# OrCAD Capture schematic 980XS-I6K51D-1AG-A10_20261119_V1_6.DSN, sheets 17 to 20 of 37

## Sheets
17 P0011_S1_POWER: size A2
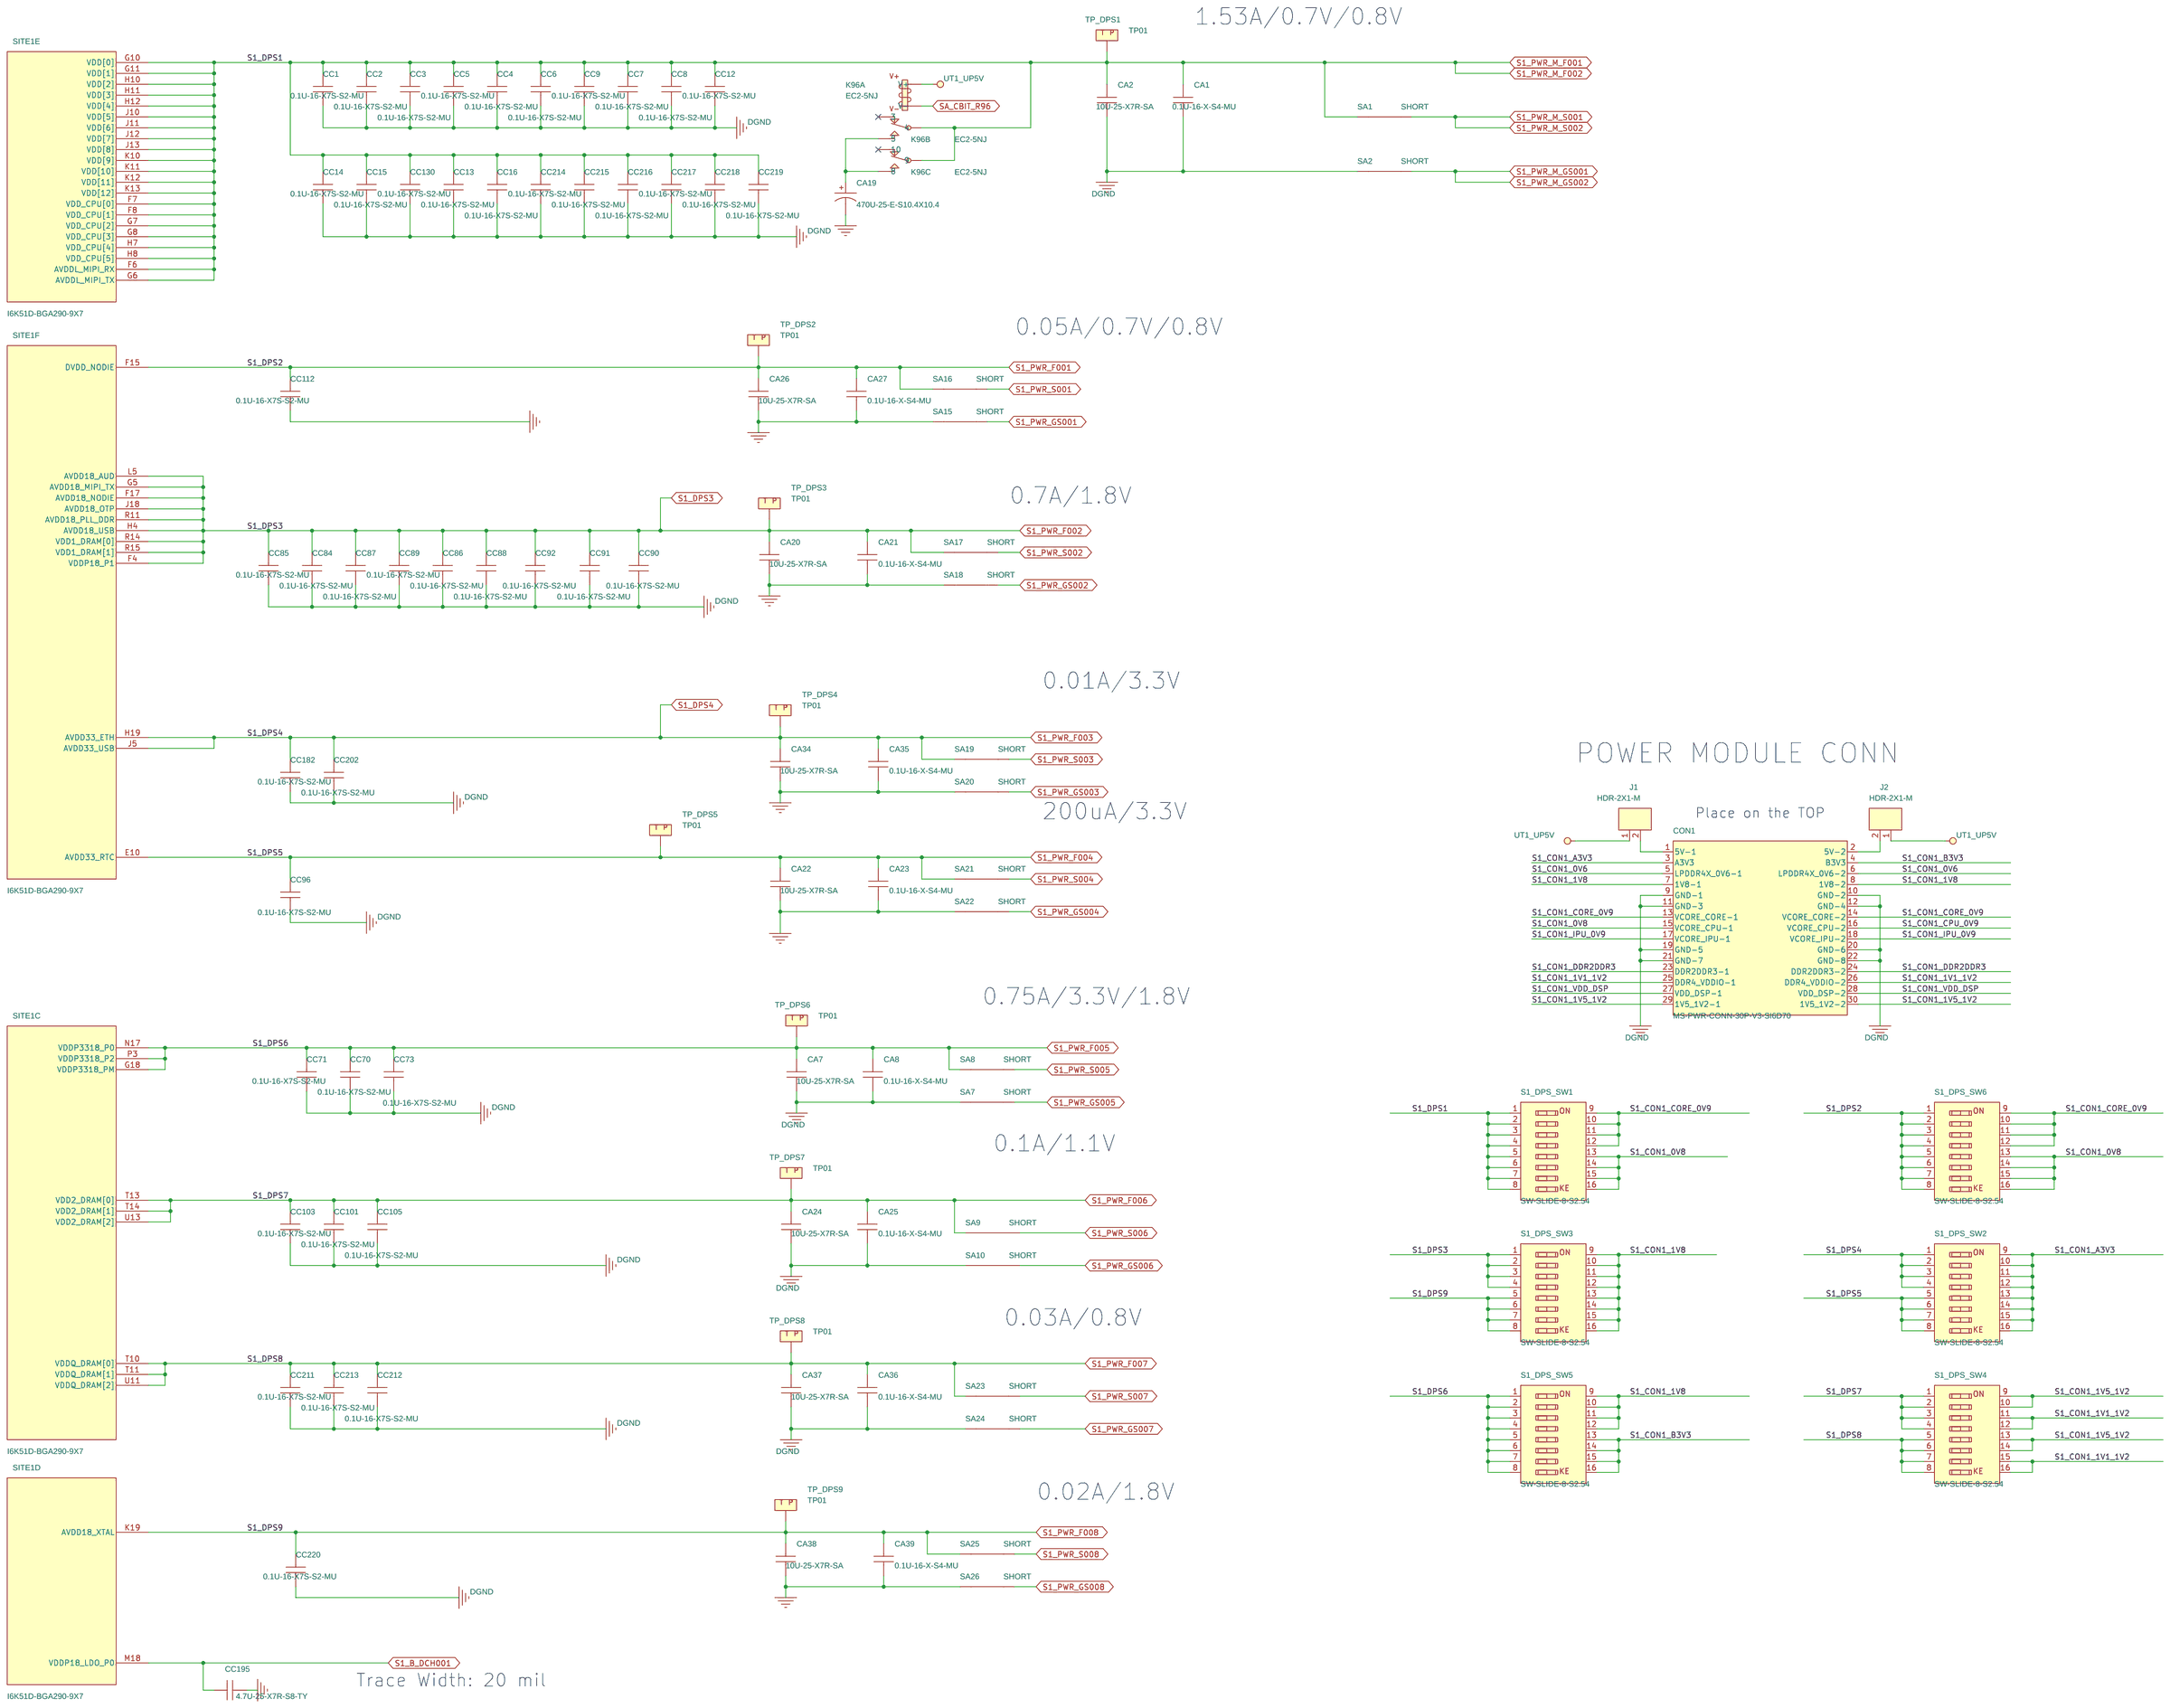
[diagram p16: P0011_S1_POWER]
18 P0013_S1_MIPI: size A2
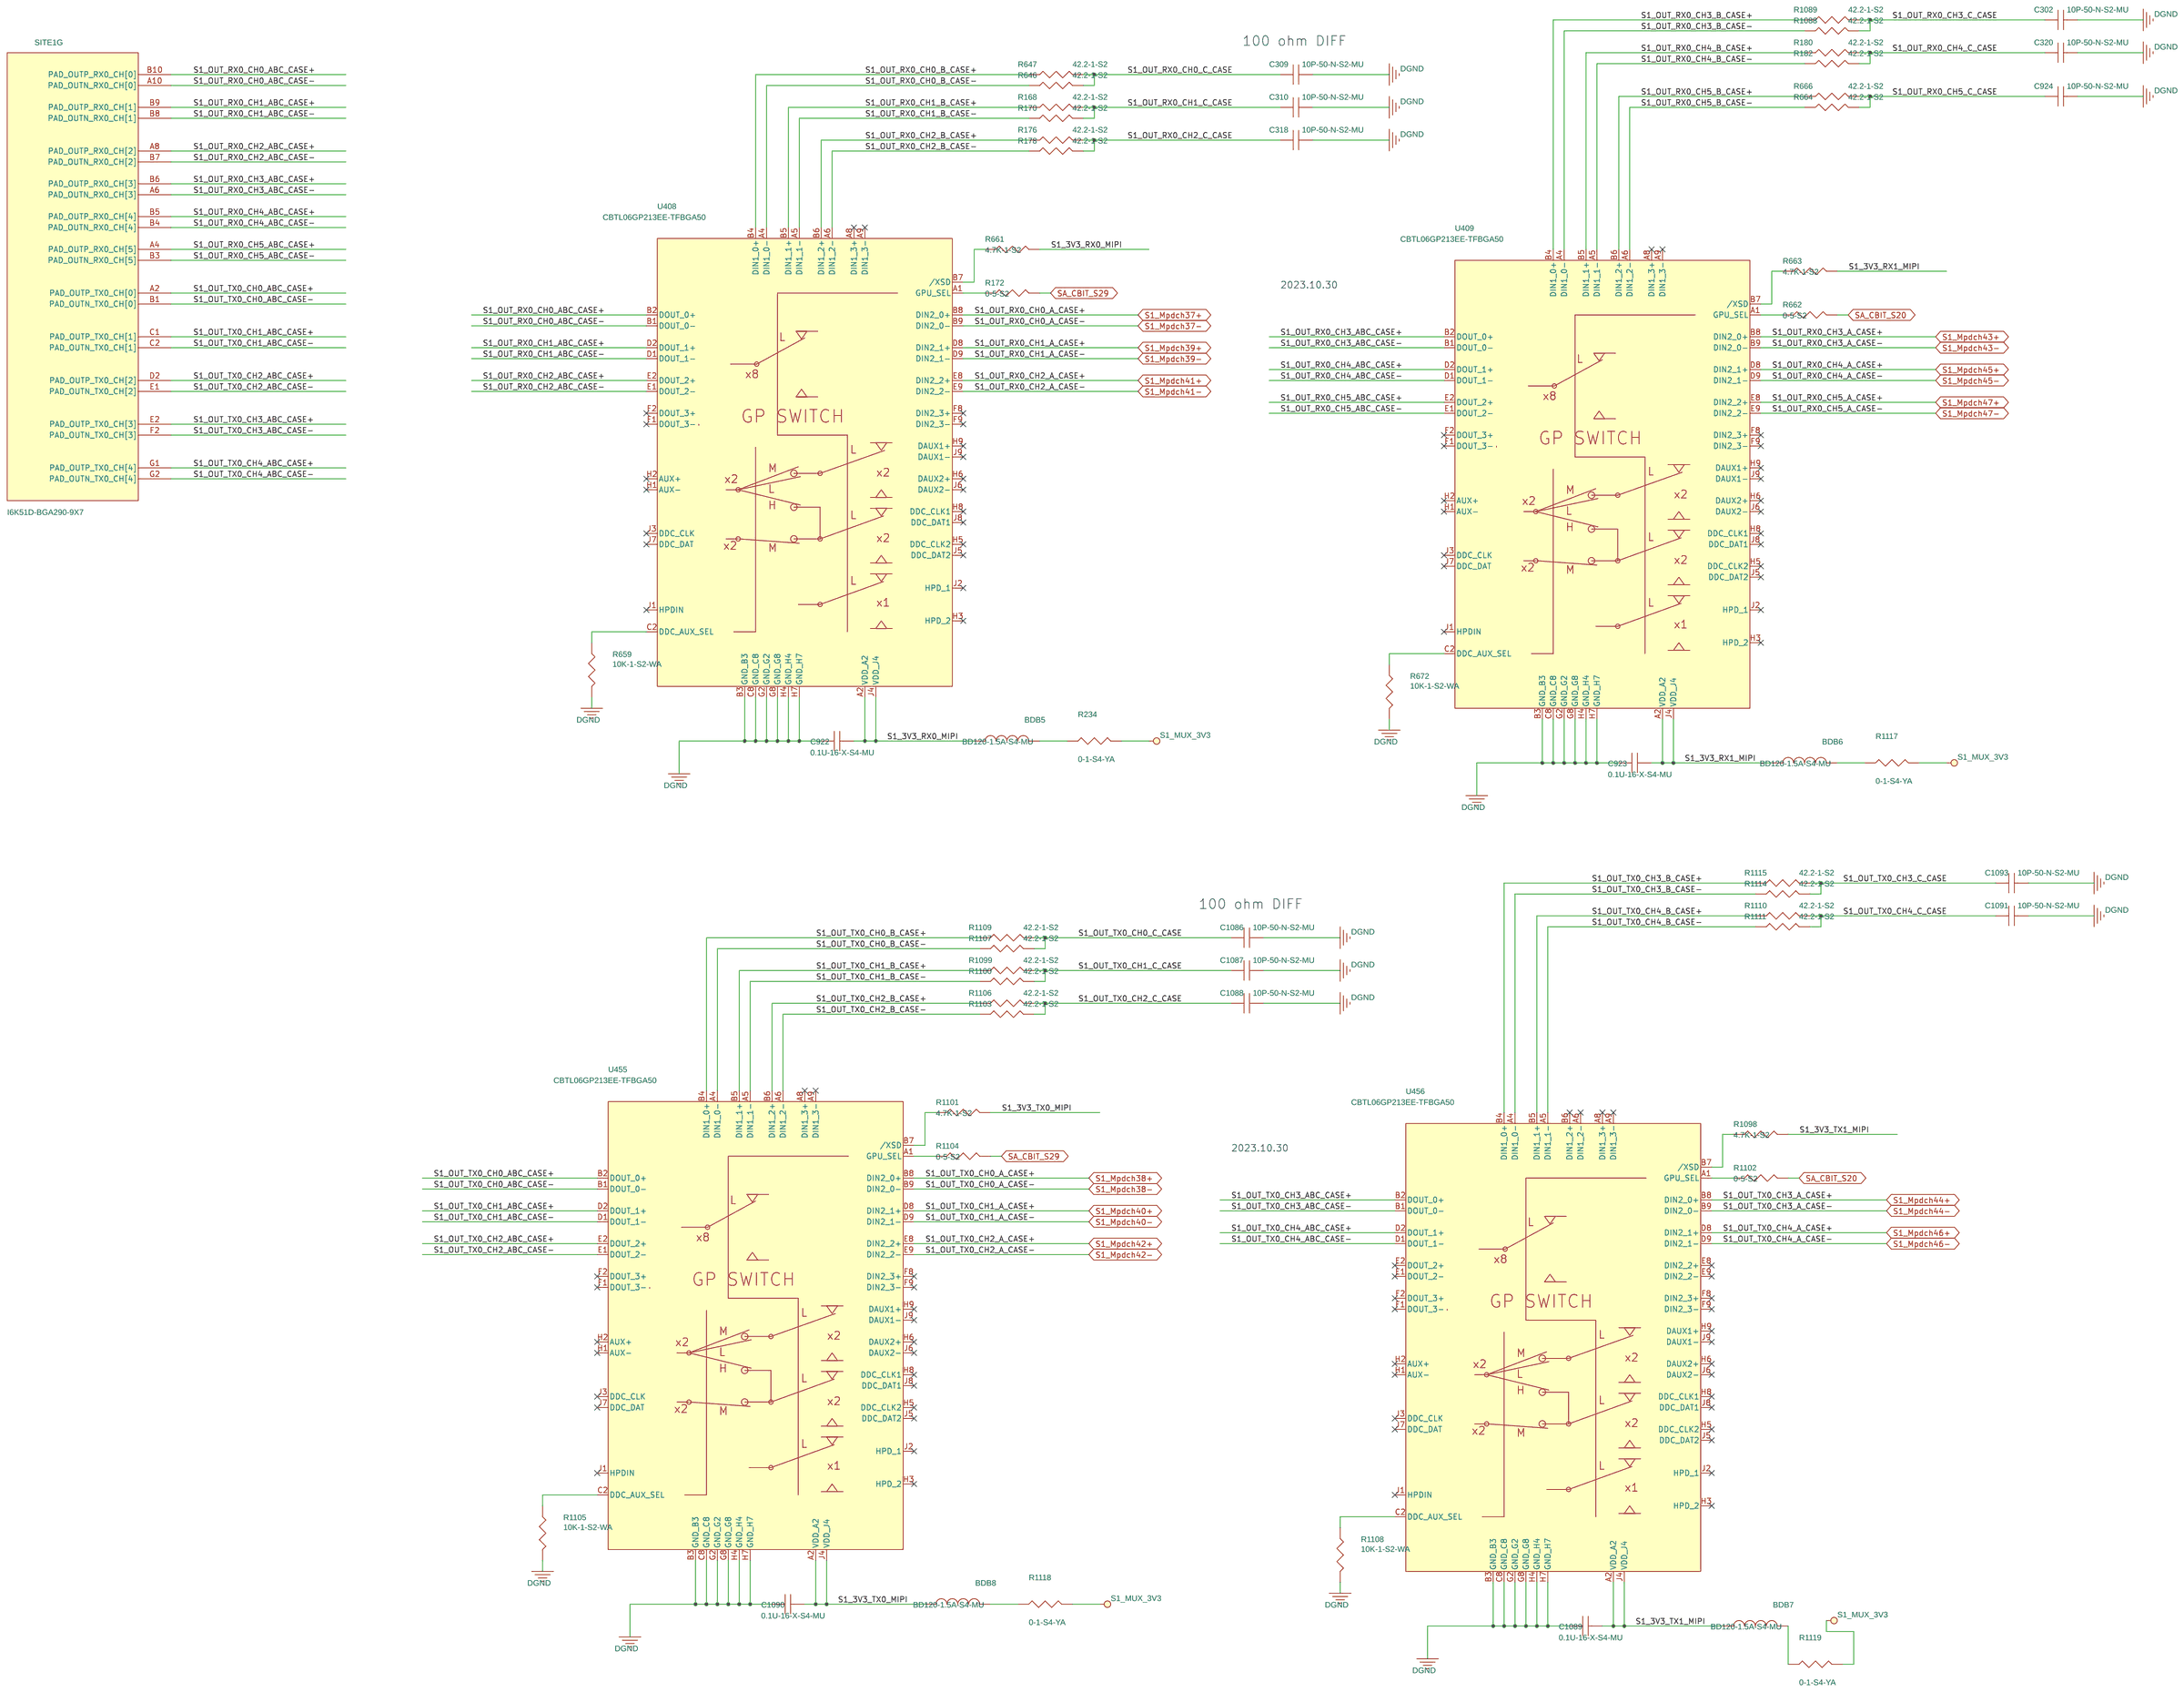
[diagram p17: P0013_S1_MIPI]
19 S500_Ubit_Buffer: size A2
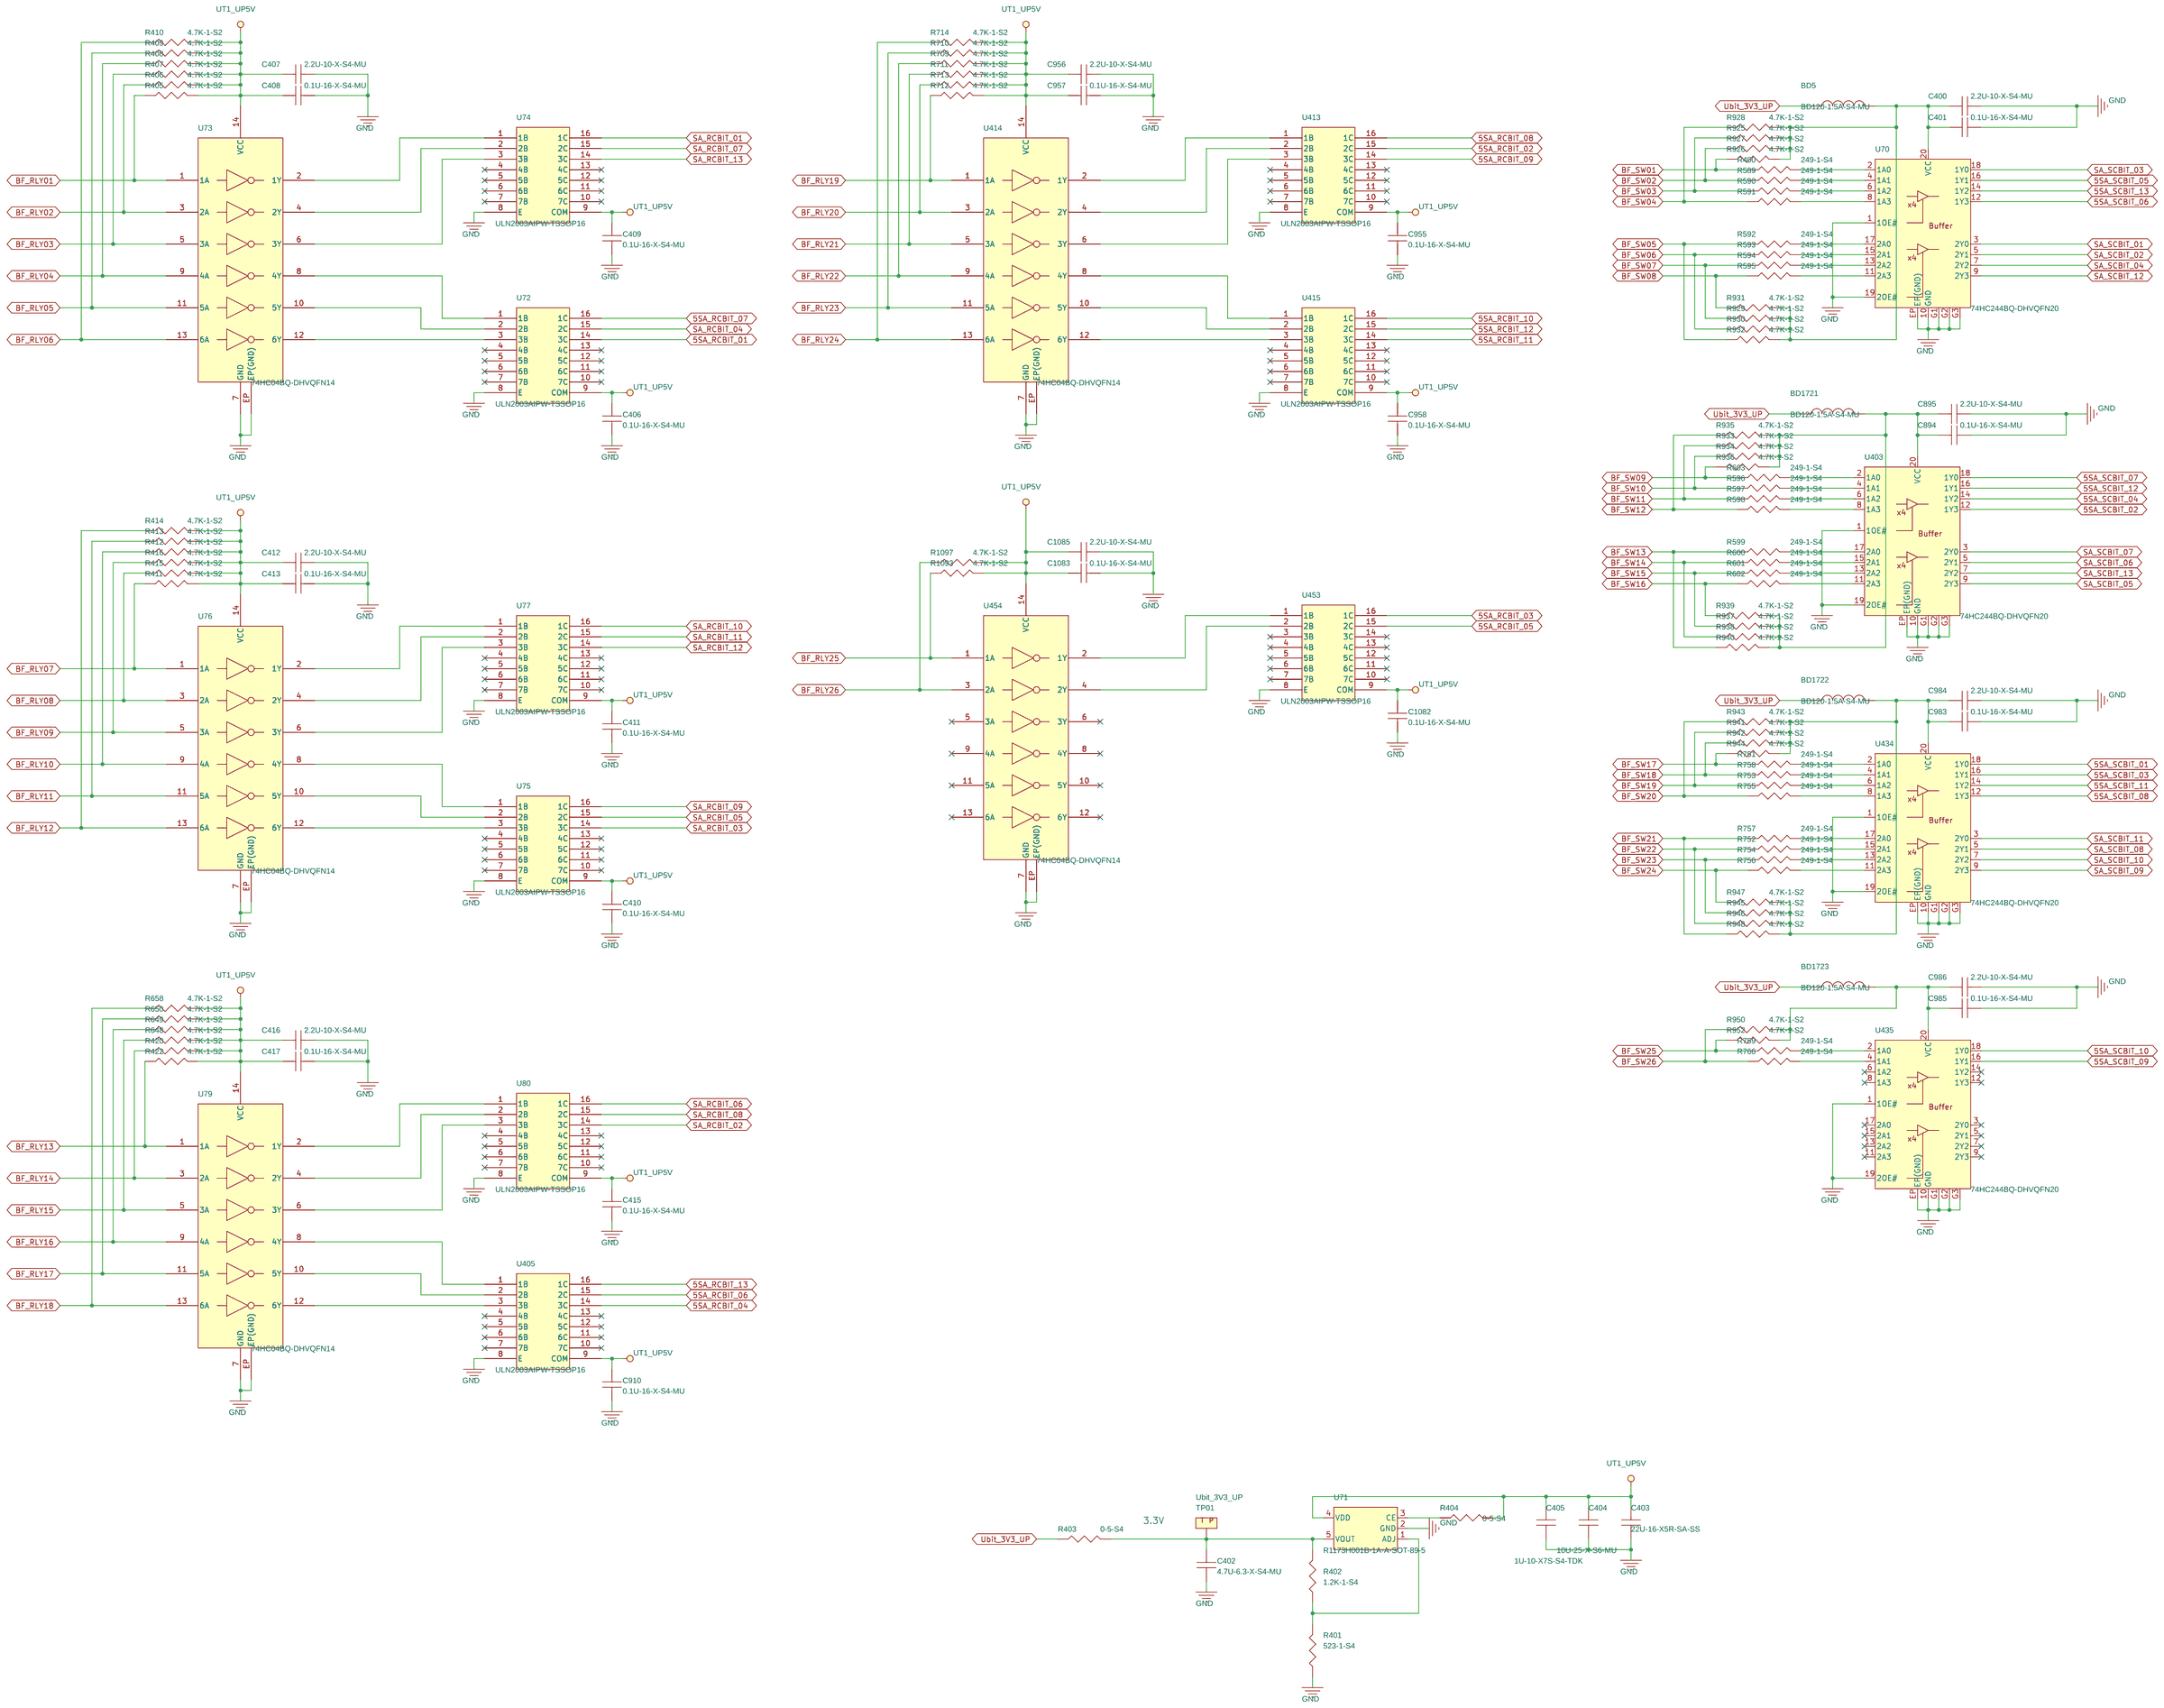
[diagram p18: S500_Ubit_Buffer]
20 S501-Support Circuits: size Custom
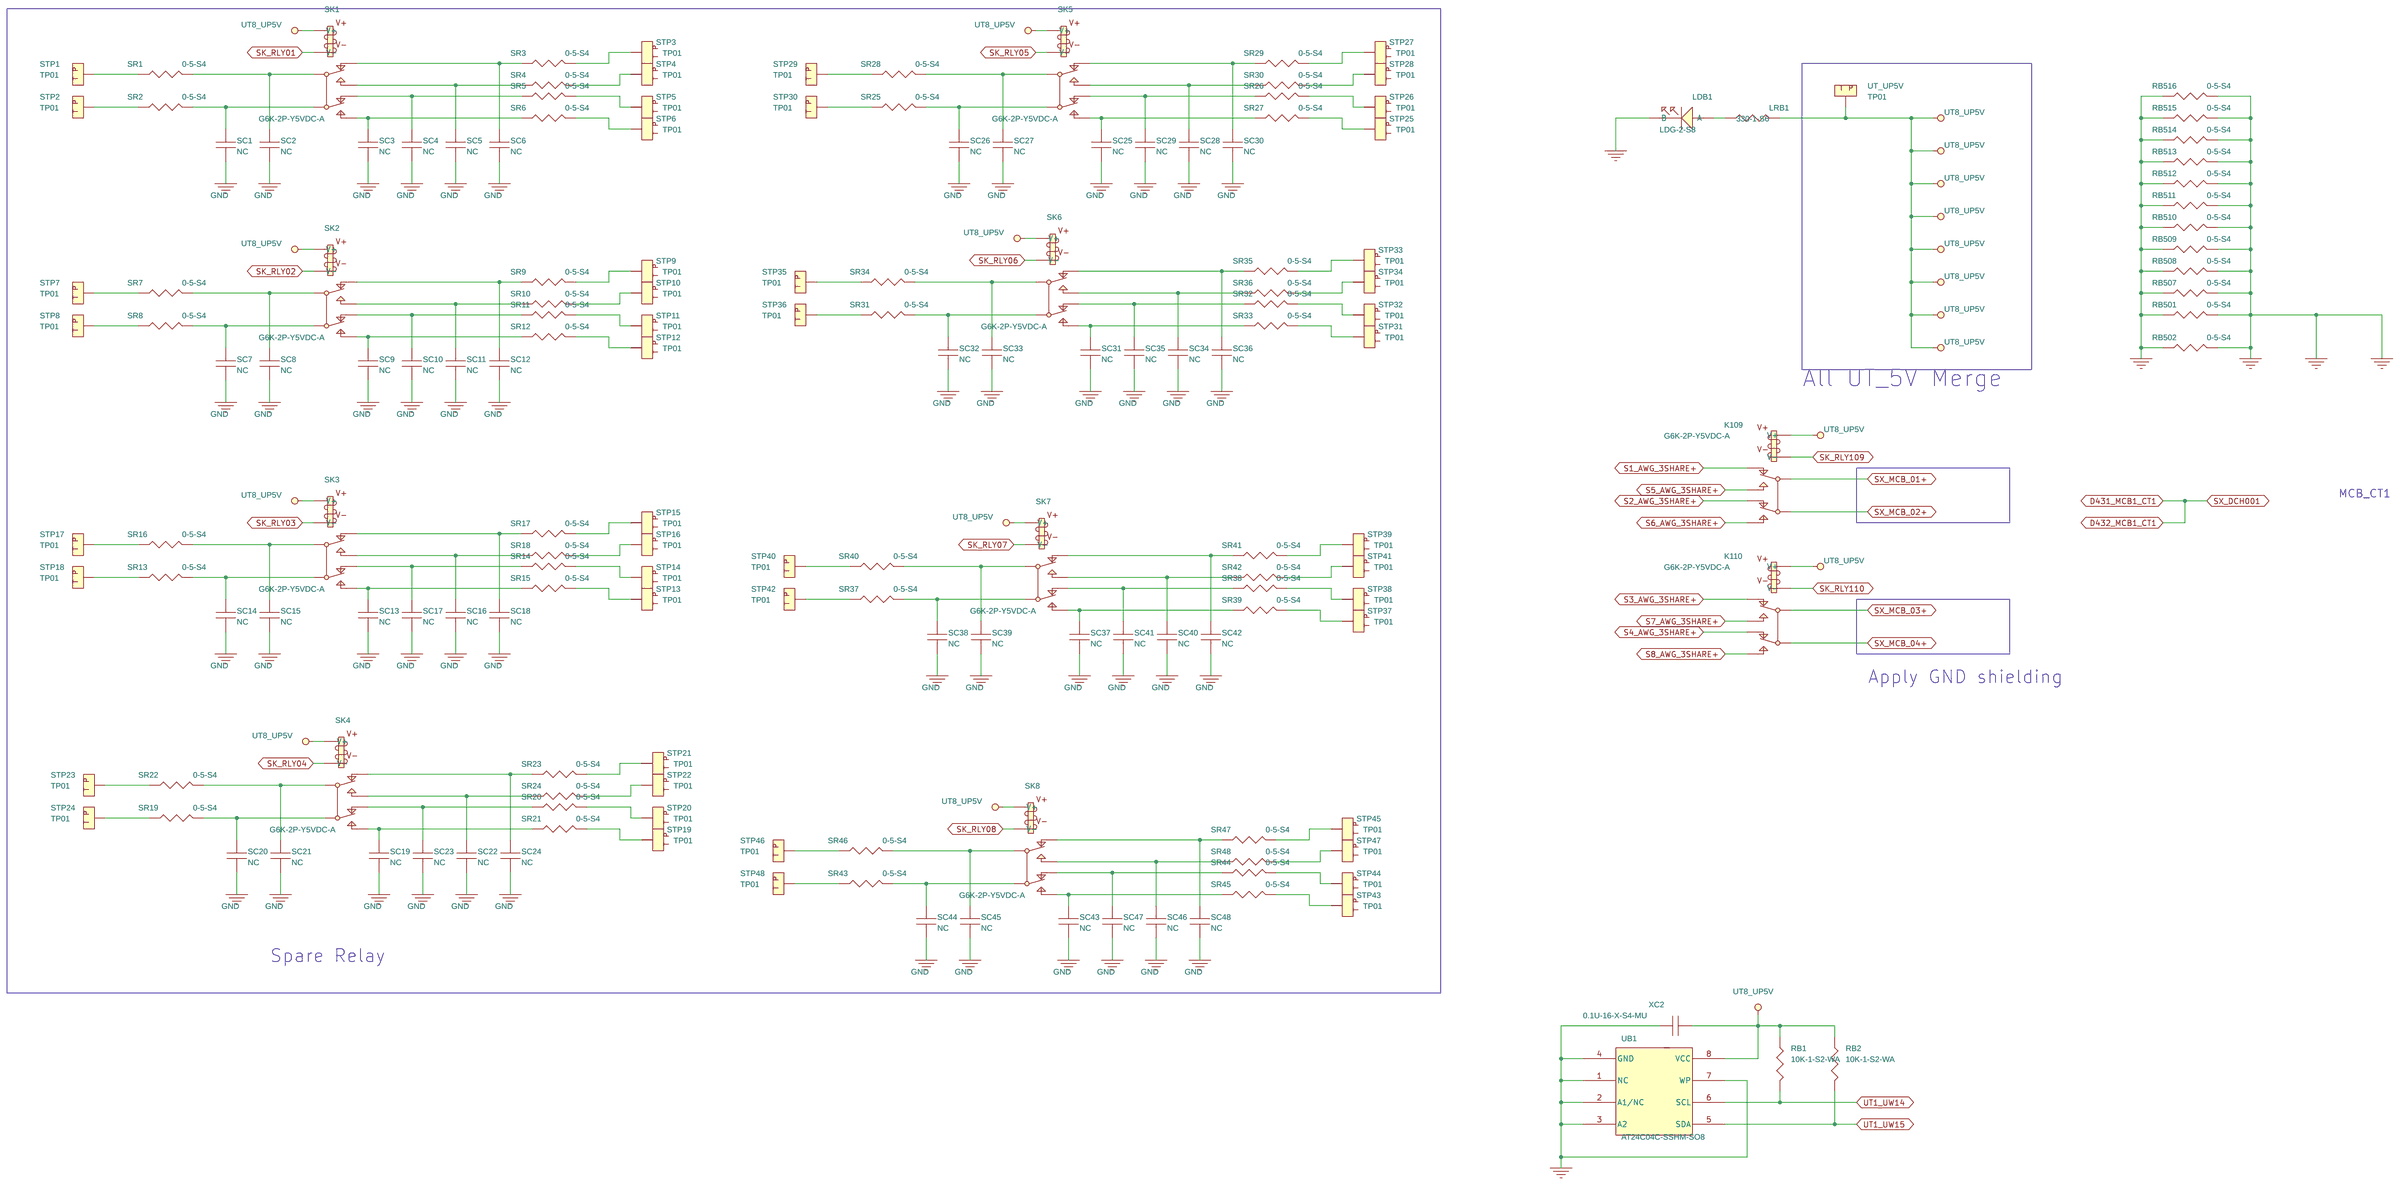
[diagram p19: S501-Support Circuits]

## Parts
sheet P0011_S1_POWER
CA1  0.1U-16-X-S4-MU  [C0402]
CA2  10U-25-X7R-SA  [C1206]
CA7  10U-25-X7R-SA  [C1206]
CA8  0.1U-16-X-S4-MU  [C0402]
CA19  470U-25-E-S10.4X10.4  [EC_10P3X10_S]
CA20  10U-25-X7R-SA  [C1206]
CA21  0.1U-16-X-S4-MU  [C0402]
CA22  10U-25-X7R-SA  [C1206]
CA23  0.1U-16-X-S4-MU  [C0402]
CA24  10U-25-X7R-SA  [C1206]
CA25  0.1U-16-X-S4-MU  [C0402]
CA26  10U-25-X7R-SA  [C1206]
CA27  0.1U-16-X-S4-MU  [C0402]
CA34  10U-25-X7R-SA  [C1206]
CA35  0.1U-16-X-S4-MU  [C0402]
CA36  0.1U-16-X-S4-MU  [C0402]
CA37  10U-25-X7R-SA  [C1206]
CA38  10U-25-X7R-SA  [C1206]
CA39  0.1U-16-X-S4-MU  [C0402]
CC1  0.1U-16-X7S-S2-MU  [C0201_MINI]
CC2  0.1U-16-X7S-S2-MU  [C0201_MINI]
CC3  0.1U-16-X7S-S2-MU  [C0201_MINI]
CC4  0.1U-16-X7S-S2-MU  [C0201_MINI]
CC5  0.1U-16-X7S-S2-MU  [C0201_MINI]
CC6  0.1U-16-X7S-S2-MU  [C0201_MINI]
CC7  0.1U-16-X7S-S2-MU  [C0201_MINI]
CC8  0.1U-16-X7S-S2-MU  [C0201_MINI]
CC9  0.1U-16-X7S-S2-MU  [C0201_MINI]
CC12  0.1U-16-X7S-S2-MU  [C0201_MINI]
CC13  0.1U-16-X7S-S2-MU  [C0201_MINI]
CC14  0.1U-16-X7S-S2-MU  [C0201_MINI]
CC15  0.1U-16-X7S-S2-MU  [C0201_MINI]
CC16  0.1U-16-X7S-S2-MU  [C0201_MINI]
CC70  0.1U-16-X7S-S2-MU  [C0201_MINI]
CC71  0.1U-16-X7S-S2-MU  [C0201_MINI]
CC73  0.1U-16-X7S-S2-MU  [C0201_MINI]
CC84  0.1U-16-X7S-S2-MU  [C0201_MINI]
CC85  0.1U-16-X7S-S2-MU  [C0201_MINI]
CC86  0.1U-16-X7S-S2-MU  [C0201_MINI]
CC87  0.1U-16-X7S-S2-MU  [C0201_MINI]
CC88  0.1U-16-X7S-S2-MU  [C0201_MINI]
CC89  0.1U-16-X7S-S2-MU  [C0201_MINI]
CC90  0.1U-16-X7S-S2-MU  [C0201_MINI]
CC91  0.1U-16-X7S-S2-MU  [C0201_MINI]
CC92  0.1U-16-X7S-S2-MU  [C0201_MINI]
CC96  0.1U-16-X7S-S2-MU  [C0201_MINI]
CC101  0.1U-16-X7S-S2-MU  [C0201_MINI]
CC103  0.1U-16-X7S-S2-MU  [C0201_MINI]
CC105  0.1U-16-X7S-S2-MU  [C0201_MINI]
CC112  0.1U-16-X7S-S2-MU  [C0201_MINI]
CC130  0.1U-16-X7S-S2-MU  [C0201_MINI]
CC182  0.1U-16-X7S-S2-MU  [C0201_MINI]
CC195  4.7U-25-X7R-S8-TY  [C0805]
CC202  0.1U-16-X7S-S2-MU  [C0201_MINI]
CC211  0.1U-16-X7S-S2-MU  [C0201_MINI]
CC212  0.1U-16-X7S-S2-MU  [C0201_MINI]
CC213  0.1U-16-X7S-S2-MU  [C0201_MINI]
CC214  0.1U-16-X7S-S2-MU  [C0201_MINI]
CC215  0.1U-16-X7S-S2-MU  [C0201_MINI]
CC216  0.1U-16-X7S-S2-MU  [C0201_MINI]
CC217  0.1U-16-X7S-S2-MU  [C0201_MINI]
CC218  0.1U-16-X7S-S2-MU  [C0201_MINI]
CC219  0.1U-16-X7S-S2-MU  [C0201_MINI]
CC220  0.1U-16-X7S-S2-MU  [C0201_MINI]
CON1  MS-PWR-CONN-30P-V3-SI6D70  [CONN_15X2_100MIL_PH_MS_V2]
J1  HDR-2X1-M  [JP_2P_100]
J2  HDR-2X1-M  [JP_2P_100]
K96  EC2-5NJ  [RL_NECEC2_10P_5V]  (sections A,B,C)
S1_DPS_SW1  SW-SLIDE-8-S2.54  [SW8X2_2P54MM_16P_SMD]
S1_DPS_SW2  SW-SLIDE-8-S2.54  [SW8X2_2P54MM_16P_SMD]
S1_DPS_SW3  SW-SLIDE-8-S2.54  [SW8X2_2P54MM_16P_SMD]
S1_DPS_SW4  SW-SLIDE-8-S2.54  [SW8X2_2P54MM_16P_SMD]
S1_DPS_SW5  SW-SLIDE-8-S2.54  [SW8X2_2P54MM_16P_SMD]
S1_DPS_SW6  SW-SLIDE-8-S2.54  [SW8X2_2P54MM_16P_SMD]
SA1  SHORT  [DEFAULT_SHORT_SMALL]
SA2  SHORT  [DEFAULT_SHORT_SMALL]
SA7  SHORT  [DEFAULT_SHORT_SMALL]
SA8  SHORT  [DEFAULT_SHORT_SMALL]
SA9  SHORT  [DEFAULT_SHORT_SMALL]
SA10  SHORT  [DEFAULT_SHORT_SMALL]
SA15  SHORT  [DEFAULT_SHORT_SMALL]
SA16  SHORT  [DEFAULT_SHORT_SMALL]
SA17  SHORT  [DEFAULT_SHORT_SMALL]
SA18  SHORT  [DEFAULT_SHORT_SMALL]
SA19  SHORT  [DEFAULT_SHORT_SMALL]
SA20  SHORT  [DEFAULT_SHORT_SMALL]
SA21  SHORT  [DEFAULT_SHORT_SMALL]
SA22  SHORT  [DEFAULT_SHORT_SMALL]
SA23  SHORT  [DEFAULT_SHORT_SMALL]
SA24  SHORT  [DEFAULT_SHORT_SMALL]
SA25  SHORT  [DEFAULT_SHORT_SMALL]
SA26  SHORT  [DEFAULT_SHORT_SMALL]
SITE1  I6K51D-BGA290-9X7  [SK_TFBGA7X9_290P_0P4MM_JG]  (sections A,B,C,D,E,F,G,H,I,J,K,L,M,N,O)
TP_DPS1  TP01  [TP_040_T]
TP_DPS2  TP01  [TP_040_T]
TP_DPS3  TP01  [TP_040_T]
TP_DPS4  TP01  [TP_040_T]
TP_DPS5  TP01  [TP_040_T]
TP_DPS6  TP01  [TP_040_T]
TP_DPS7  TP01  [TP_040_T]
TP_DPS8  TP01  [TP_040_T]
TP_DPS9  TP01  [TP_040_T]
sheet P0013_S1_MIPI
BDB5  BD120-1.5A-S4-MU  [FB0402]
BDB6  BD120-1.5A-S4-MU  [FB0402]
BDB7  BD120-1.5A-S4-MU  [FB0402]
BDB8  BD120-1.5A-S4-MU  [FB0402]
C302  10P-50-N-S2-MU  [C0201]
C309  10P-50-N-S2-MU  [C0201]
C310  10P-50-N-S2-MU  [C0201]
C318  10P-50-N-S2-MU  [C0201]
C320  10P-50-N-S2-MU  [C0201]
C922  0.1U-16-X-S4-MU  [C0402]
C923  0.1U-16-X-S4-MU  [C0402]
C924  10P-50-N-S2-MU  [C0201]
C1086  10P-50-N-S2-MU  [C0201]
C1087  10P-50-N-S2-MU  [C0201]
C1088  10P-50-N-S2-MU  [C0201]
C1089  0.1U-16-X-S4-MU  [C0402]
C1090  0.1U-16-X-S4-MU  [C0402]
C1091  10P-50-N-S2-MU  [C0201]
C1093  10P-50-N-S2-MU  [C0201]
R168  42.2-1-S2  [R0201]
R170  42.2-1-S2  [R0201]
R172  0-5-S2  [R0201]
R176  42.2-1-S2  [R0201]
R178  42.2-1-S2  [R0201]
R180  42.2-1-S2  [R0201]
R182  42.2-1-S2  [R0201]
R234  0-1-S4-YA  [R0402]
R646  42.2-1-S2  [R0201]
R647  42.2-1-S2  [R0201]
R659  10K-1-S2-WA  [R0201]
R661  4.7K-1-S2  [R0201]
R662  0-5-S2  [R0201]
R663  4.7K-1-S2  [R0201]
R664  42.2-1-S2  [R0201]
R666  42.2-1-S2  [R0201]
R672  10K-1-S2-WA  [R0201]
R1088  42.2-1-S2  [R0201]
R1089  42.2-1-S2  [R0201]
R1098  4.7K-1-S2  [R0201]
R1099  42.2-1-S2  [R0201]
R1100  42.2-1-S2  [R0201]
R1101  4.7K-1-S2  [R0201]
R1102  0-5-S2  [R0201]
R1103  42.2-1-S2  [R0201]
R1104  0-5-S2  [R0201]
R1105  10K-1-S2-WA  [R0201]
R1106  42.2-1-S2  [R0201]
R1107  42.2-1-S2  [R0201]
R1108  10K-1-S2-WA  [R0201]
R1109  42.2-1-S2  [R0201]
R1110  42.2-1-S2  [R0201]
R1111  42.2-1-S2  [R0201]
R1114  42.2-1-S2  [R0201]
R1115  42.2-1-S2  [R0201]
R1117  0-1-S4-YA  [R0402]
R1118  0-1-S4-YA  [R0402]
R1119  0-1-S4-YA  [R0402]
U408  CBTL06GP213EE-TFBGA50  [TFBGA9X9_50P_0P5MM]
U409  CBTL06GP213EE-TFBGA50  [TFBGA9X9_50P_0P5MM]
U455  CBTL06GP213EE-TFBGA50  [TFBGA9X9_50P_0P5MM]
U456  CBTL06GP213EE-TFBGA50  [TFBGA9X9_50P_0P5MM]
sheet S500_Ubit_Buffer
BD5  BD120-1.5A-S4-MU  [FB0402]
BD1721  BD120-1.5A-S4-MU  [FB0402]
BD1722  BD120-1.5A-S4-MU  [FB0402]
BD1723  BD120-1.5A-S4-MU  [FB0402]
C400  2.2U-10-X-S4-MU  [C0402]
C401  0.1U-16-X-S4-MU  [C0402]
C402  4.7U-6.3-X-S4-MU  [C0402]
C403  22U-16-X5R-SA-SS  [C1206]
C404  10U-25-X-S6-MU  [C0603]
C405  1U-10-X7S-S4-TDK  [C0402]
C406  0.1U-16-X-S4-MU  [C0402]
C407  2.2U-10-X-S4-MU  [C0402]
C408  0.1U-16-X-S4-MU  [C0402]
C409  0.1U-16-X-S4-MU  [C0402]
C410  0.1U-16-X-S4-MU  [C0402]
C411  0.1U-16-X-S4-MU  [C0402]
C412  2.2U-10-X-S4-MU  [C0402]
C413  0.1U-16-X-S4-MU  [C0402]
C415  0.1U-16-X-S4-MU  [C0402]
C416  2.2U-10-X-S4-MU  [C0402]
C417  0.1U-16-X-S4-MU  [C0402]
C894  0.1U-16-X-S4-MU  [C0402]
C895  2.2U-10-X-S4-MU  [C0402]
C910  0.1U-16-X-S4-MU  [C0402]
C955  0.1U-16-X-S4-MU  [C0402]
C956  2.2U-10-X-S4-MU  [C0402]
C957  0.1U-16-X-S4-MU  [C0402]
C958  0.1U-16-X-S4-MU  [C0402]
C983  0.1U-16-X-S4-MU  [C0402]
C984  2.2U-10-X-S4-MU  [C0402]
C985  0.1U-16-X-S4-MU  [C0402]
C986  2.2U-10-X-S4-MU  [C0402]
C1082  0.1U-16-X-S4-MU  [C0402]
C1083  0.1U-16-X-S4-MU  [C0402]
C1085  2.2U-10-X-S4-MU  [C0402]
R400  249-1-S4  [R0402]
R401  523-1-S4  [R0402]
R402  1.2K-1-S4  [R0402]
R403  0-5-S4  [R0402]
R404  0-5-S4  [R0402]
R405  4.7K-1-S2  [R0201]
R406  4.7K-1-S2  [R0201]
R407  4.7K-1-S2  [R0201]
R408  4.7K-1-S2  [R0201]
R409  4.7K-1-S2  [R0201]
R410  4.7K-1-S2  [R0201]
R411  4.7K-1-S2  [R0201]
R412  4.7K-1-S2  [R0201]
R413  4.7K-1-S2  [R0201]
R414  4.7K-1-S2  [R0201]
R415  4.7K-1-S2  [R0201]
R416  4.7K-1-S2  [R0201]
R420  4.7K-1-S2  [R0201]
R422  4.7K-1-S2  [R0201]
R589  249-1-S4  [R0402]
R590  249-1-S4  [R0402]
R591  249-1-S4  [R0402]
R592  249-1-S4  [R0402]
R593  249-1-S4  [R0402]
R594  249-1-S4  [R0402]
R595  249-1-S4  [R0402]
R596  249-1-S4  [R0402]
R597  249-1-S4  [R0402]
R598  249-1-S4  [R0402]
R599  249-1-S4  [R0402]
R600  249-1-S4  [R0402]
R601  249-1-S4  [R0402]
R602  249-1-S4  [R0402]
R603  249-1-S4  [R0402]
R648  4.7K-1-S2  [R0201]
R649  4.7K-1-S2  [R0201]
R650  4.7K-1-S2  [R0201]
R658  4.7K-1-S2  [R0201]
R709  4.7K-1-S2  [R0201]
R710  4.7K-1-S2  [R0201]
R711  4.7K-1-S2  [R0201]
R712  4.7K-1-S2  [R0201]
R713  4.7K-1-S2  [R0201]
R714  4.7K-1-S2  [R0201]
R751  249-1-S4  [R0402]
R752  249-1-S4  [R0402]
R753  249-1-S4  [R0402]
R754  249-1-S4  [R0402]
R755  249-1-S4  [R0402]
R756  249-1-S4  [R0402]
R757  249-1-S4  [R0402]
R758  249-1-S4  [R0402]
R759  249-1-S4  [R0402]
R766  249-1-S4  [R0402]
R925  4.7K-1-S2  [R0201]
R926  4.7K-1-S2  [R0201]
R927  4.7K-1-S2  [R0201]
R928  4.7K-1-S2  [R0201]
R929  4.7K-1-S2  [R0201]
R930  4.7K-1-S2  [R0201]
R931  4.7K-1-S2  [R0201]
R932  4.7K-1-S2  [R0201]
R933  4.7K-1-S2  [R0201]
R934  4.7K-1-S2  [R0201]
R935  4.7K-1-S2  [R0201]
R936  4.7K-1-S2  [R0201]
R937  4.7K-1-S2  [R0201]
R938  4.7K-1-S2  [R0201]
R939  4.7K-1-S2  [R0201]
R940  4.7K-1-S2  [R0201]
R941  4.7K-1-S2  [R0201]
R942  4.7K-1-S2  [R0201]
R943  4.7K-1-S2  [R0201]
R944  4.7K-1-S2  [R0201]
R945  4.7K-1-S2  [R0201]
R946  4.7K-1-S2  [R0201]
R947  4.7K-1-S2  [R0201]
R948  4.7K-1-S2  [R0201]
R950  4.7K-1-S2  [R0201]
R952  4.7K-1-S2  [R0201]
R1093  4.7K-1-S2  [R0201]
R1097  4.7K-1-S2  [R0201]
U70  74HC244BQ-DHVQFN20  [VQFN2P6X4P6_20P_0P5MM_EP]
U71  R1173H001B-1A-A-SOT-89-5  [SOT_89_5]
U72  ULN2003AIPW-TSSOP16  [TSSOP16_228X065MM]
U73  74HC04BQ-DHVQFN14  [SO14_0P5_14P_74HC14]
U74  ULN2003AIPW-TSSOP16  [TSSOP16_228X065MM]
U75  ULN2003AIPW-TSSOP16  [TSSOP16_228X065MM]
U76  74HC04BQ-DHVQFN14  [SO14_0P5_14P_74HC14]
U77  ULN2003AIPW-TSSOP16  [TSSOP16_228X065MM]
U79  74HC04BQ-DHVQFN14  [SO14_0P5_14P_74HC14]
U80  ULN2003AIPW-TSSOP16  [TSSOP16_228X065MM]
U403  74HC244BQ-DHVQFN20  [VQFN2P6X4P6_20P_0P5MM_EP]
U405  ULN2003AIPW-TSSOP16  [TSSOP16_228X065MM]
U413  ULN2003AIPW-TSSOP16  [TSSOP16_228X065MM]
U414  74HC04BQ-DHVQFN14  [SO14_0P5_14P_74HC14]
U415  ULN2003AIPW-TSSOP16  [TSSOP16_228X065MM]
U434  74HC244BQ-DHVQFN20  [VQFN2P6X4P6_20P_0P5MM_EP]
U435  74HC244BQ-DHVQFN20  [VQFN2P6X4P6_20P_0P5MM_EP]
U453  ULN2003AIPW-TSSOP16  [TSSOP16_228X065MM]
U454  74HC04BQ-DHVQFN14  [SO14_0P5_14P_74HC14]
Ubit_3V3_UP  TP01  [TP_040_T]
sheet S501-Support Circuits
K109  G6K-2P-Y5VDC-A  [RL_OMRONG6K2PY_5V]
K110  G6K-2P-Y5VDC-A  [RL_OMRONG6K2PY_5V]
LDB1  LDG-2-S8  [LED_0805]
LRB1  330-1-S6  [R0603]
RB1  10K-1-S2-WA  [R0201]
RB2  10K-1-S2-WA  [R0201]
RB501  0-5-S4  [R0402]
RB502  0-5-S4  [R0402]
RB507  0-5-S4  [R0402]
RB508  0-5-S4  [R0402]
RB509  0-5-S4  [R0402]
RB510  0-5-S4  [R0402]
RB511  0-5-S4  [R0402]
RB512  0-5-S4  [R0402]
RB513  0-5-S4  [R0402]
RB514  0-5-S4  [R0402]
RB515  0-5-S4  [R0402]
RB516  0-5-S4  [R0402]
SC1  NC  [C0402_UNBGA_V2]
SC2  NC  [C0402_UNBGA_V2]
SC3  NC  [C0402_UNBGA_V2]
SC4  NC  [C0402_UNBGA_V2]
SC5  NC  [C0402_UNBGA_V2]
SC6  NC  [C0402_UNBGA_V2]
SC7  NC  [C0402_UNBGA_V2]
SC8  NC  [C0402_UNBGA_V2]
SC9  NC  [C0402_UNBGA_V2]
SC10  NC  [C0402_UNBGA_V2]
SC11  NC  [C0402_UNBGA_V2]
SC12  NC  [C0402_UNBGA_V2]
SC13  NC  [C0402_UNBGA_V2]
SC14  NC  [C0402_UNBGA_V2]
SC15  NC  [C0402_UNBGA_V2]
SC16  NC  [C0402_UNBGA_V2]
SC17  NC  [C0402_UNBGA_V2]
SC18  NC  [C0402_UNBGA_V2]
SC19  NC  [C0402_UNBGA_V2]
SC20  NC  [C0402_UNBGA_V2]
SC21  NC  [C0402_UNBGA_V2]
SC22  NC  [C0402_UNBGA_V2]
SC23  NC  [C0402_UNBGA_V2]
SC24  NC  [C0402_UNBGA_V2]
SC25  NC  [C0402_UNBGA_V2]
SC26  NC  [C0402_UNBGA_V2]
SC27  NC  [C0402_UNBGA_V2]
SC28  NC  [C0402_UNBGA_V2]
SC29  NC  [C0402_UNBGA_V2]
SC30  NC  [C0402_UNBGA_V2]
SC31  NC  [C0402_UNBGA_V2]
SC32  NC  [C0402_UNBGA_V2]
SC33  NC  [C0402_UNBGA_V2]
SC34  NC  [C0402_UNBGA_V2]
SC35  NC  [C0402_UNBGA_V2]
SC36  NC  [C0402_UNBGA_V2]
SC37  NC  [C0402_UNBGA_V2]
SC38  NC  [C0402_UNBGA_V2]
SC39  NC  [C0402_UNBGA_V2]
SC40  NC  [C0402_UNBGA_V2]
SC41  NC  [C0402_UNBGA_V2]
SC42  NC  [C0402_UNBGA_V2]
SC43  NC  [C0402_UNBGA_V2]
SC44  NC  [C0402_UNBGA_V2]
SC45  NC  [C0402_UNBGA_V2]
SC46  NC  [C0402_UNBGA_V2]
SC47  NC  [C0402_UNBGA_V2]
SC48  NC  [C0402_UNBGA_V2]
SK1  G6K-2P-Y5VDC-A  [RL_OMRONG6K2PY_5V]
SK2  G6K-2P-Y5VDC-A  [RL_OMRONG6K2PY_5V]
SK3  G6K-2P-Y5VDC-A  [RL_OMRONG6K2PY_5V]
SK4  G6K-2P-Y5VDC-A  [RL_OMRONG6K2PY_5V]
SK5  G6K-2P-Y5VDC-A  [RL_OMRONG6K2PY_5V]
SK6  G6K-2P-Y5VDC-A  [RL_OMRONG6K2PY_5V]
SK7  G6K-2P-Y5VDC-A  [RL_OMRONG6K2PY_5V]
SK8  G6K-2P-Y5VDC-A  [RL_OMRONG6K2PY_5V]
SR1  0-5-S4  [R0402]
SR2  0-5-S4  [R0402]
SR3  0-5-S4  [R0402]
SR4  0-5-S4  [R0402]
SR5  0-5-S4  [R0402]
SR6  0-5-S4  [R0402]
SR7  0-5-S4  [R0402]
SR8  0-5-S4  [R0402]
SR9  0-5-S4  [R0402]
SR10  0-5-S4  [R0402]
SR11  0-5-S4  [R0402]
SR12  0-5-S4  [R0402]
SR13  0-5-S4  [R0402]
SR14  0-5-S4  [R0402]
SR15  0-5-S4  [R0402]
SR16  0-5-S4  [R0402]
SR17  0-5-S4  [R0402]
SR18  0-5-S4  [R0402]
SR19  0-5-S4  [R0402]
SR20  0-5-S4  [R0402]
SR21  0-5-S4  [R0402]
SR22  0-5-S4  [R0402]
SR23  0-5-S4  [R0402]
SR24  0-5-S4  [R0402]
SR25  0-5-S4  [R0402]
SR26  0-5-S4  [R0402]
SR27  0-5-S4  [R0402]
SR28  0-5-S4  [R0402]
SR29  0-5-S4  [R0402]
SR30  0-5-S4  [R0402]
SR31  0-5-S4  [R0402]
SR32  0-5-S4  [R0402]
SR33  0-5-S4  [R0402]
SR34  0-5-S4  [R0402]
SR35  0-5-S4  [R0402]
SR36  0-5-S4  [R0402]
SR37  0-5-S4  [R0402]
SR38  0-5-S4  [R0402]
SR39  0-5-S4  [R0402]
SR40  0-5-S4  [R0402]
SR41  0-5-S4  [R0402]
SR42  0-5-S4  [R0402]
SR43  0-5-S4  [R0402]
SR44  0-5-S4  [R0402]
SR45  0-5-S4  [R0402]
SR46  0-5-S4  [R0402]
SR47  0-5-S4  [R0402]
SR48  0-5-S4  [R0402]
STP1  TP01  [TP_040_T]
STP2  TP01  [TP_040_T]
STP3  TP01  [TP_040_T]
STP4  TP01  [TP_040_T]
STP5  TP01  [TP_040_T]
STP6  TP01  [TP_040_T]
STP7  TP01  [TP_040_T]
STP8  TP01  [TP_040_T]
STP9  TP01  [TP_040_T]
STP10  TP01  [TP_040_T]
STP11  TP01  [TP_040_T]
STP12  TP01  [TP_040_T]
STP13  TP01  [TP_040_T]
STP14  TP01  [TP_040_T]
STP15  TP01  [TP_040_T]
STP16  TP01  [TP_040_T]
STP17  TP01  [TP_040_T]
STP18  TP01  [TP_040_T]
STP19  TP01  [TP_040_T]
STP20  TP01  [TP_040_T]
STP21  TP01  [TP_040_T]
STP22  TP01  [TP_040_T]
STP23  TP01  [TP_040_T]
STP24  TP01  [TP_040_T]
STP25  TP01  [TP_040_T]
STP26  TP01  [TP_040_T]
STP27  TP01  [TP_040_T]
STP28  TP01  [TP_040_T]
STP29  TP01  [TP_040_T]
STP30  TP01  [TP_040_T]
STP31  TP01  [TP_040_T]
STP32  TP01  [TP_040_T]
STP33  TP01  [TP_040_T]
STP34  TP01  [TP_040_T]
STP35  TP01  [TP_040_T]
STP36  TP01  [TP_040_T]
STP37  TP01  [TP_040_T]
STP38  TP01  [TP_040_T]
STP39  TP01  [TP_040_T]
STP40  TP01  [TP_040_T]
STP41  TP01  [TP_040_T]
STP42  TP01  [TP_040_T]
STP43  TP01  [TP_040_T]
STP44  TP01  [TP_040_T]
STP45  TP01  [TP_040_T]
STP46  TP01  [TP_040_T]
STP47  TP01  [TP_040_T]
STP48  TP01  [TP_040_T]
UB1  AT24C04C-SSHM-SO8  [SO8_215X127MM]
UT_UP5V  TP01  [TP_040_T]
XC2  0.1U-16-X-S4-MU  [C0402]

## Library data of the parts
C401 C406 C408-C411 C413 C415 C417 C894 C910 C922 C923 C955 C957 C958 C983 C985 CA1 CA8 CA21 CA23 CA25 CA27 XC2 = 0.1U-16-X-S4-MU
CA2 CA7 CA20 CA22 CA24 CA26 = 10U-25-X7R-SA
CA19 = 470U-25-E-S10.4X10.4
CA34 CA38 = 10U-25-X7R-SA: KAIROSNAME: CA20
CA35 CA39 = 0.1U-16-X-S4-MU: KAIROSNAME: CA21
CA36 = 0.1U-16-X-S4-MU: KAIROSNAME: CA25
CA37 = 10U-25-X7R-SA: KAIROSNAME: CA24
CC1-CC9 CC12 CC70 CC71 CC73 CC84-CC89 CC96 CC101 CC103 CC105 CC112 = 0.1U-16-X7S-S2-MU
CC13 CC15 = 0.1U-16-X7S-S2-MU: KAIROSNAME: CC2
CC14 CC16 CC130 CC214-CC219 = 0.1U-16-X7S-S2-MU: KAIROSNAME: CC1
CC90-CC92 = 0.1U-16-X7S-S2-MU: KAIROSNAME: CC88
CC182 CC202 CC220 = 0.1U-16-X7S-S2-MU: KAIROSNAME: CC85
CC195 = 4.7U-25-X7R-S8-TY
CC211 = 0.1U-16-X7S-S2-MU: KAIROSNAME: CC103
CC212 = 0.1U-16-X7S-S2-MU: KAIROSNAME: CC105
CC213 = 0.1U-16-X7S-S2-MU: KAIROSNAME: CC101
CON1 = MS-PWR-CONN-30P-V3-SI6D70
J1 J2 = HDR-2X1-M
K96 = EC2-5NJ: KAIROSNAME: K95B
S1_DPS_SW1-S1_DPS_SW6 = SW-SLIDE-8-S2.54
SA1 SA2 SA7-SA10 = SHORT
SA15 SA18 SA20 SA22 SA26 = SHORT: KAIROSNAME: SA2
SA16 SA17 SA19 SA21 SA25 = SHORT: KAIROSNAME: SA1
SA23 = SHORT: KAIROSNAME: SA9
SA24 = SHORT: KAIROSNAME: SA10
SITE1 = I6K51D-BGA290-9X7
STP1-STP48 TP_DPS1 = TP01
TP_DPS2 = TP01: KAIROSNAME: S1_DPS3
TP_DPS3 TP_DPS4 TP_DPS9 = TP01: KAIROSNAME: S1_DPS4
TP_DPS5 = TP01: KAIROSNAME: S1_DPS5
TP_DPS6 = TP01: KAIROSNAME: TP_DPS8
TP_DPS7 TP_DPS8 = TP01: KAIROSNAME: TP_DPS2
BD5 BD1721-BD1723 BDB5 BDB6 = BD120-1.5A-S4-MU
BDB7 = BD120-1.5A-S4-MU: KAIROSNAME: BDB6
BDB8 = BD120-1.5A-S4-MU: KAIROSNAME: BDB5
C302 C1088 C1093 = 10P-50-N-S2-MU: KAIROSNAME: C318
C309 C310 C318 C320 C924 = 10P-50-N-S2-MU
C1086 = 10P-50-N-S2-MU: KAIROSNAME: C309
C1087 = 10P-50-N-S2-MU: KAIROSNAME: C310
C1089 = 0.1U-16-X-S4-MU: KAIROSNAME: C923
C1090 = 0.1U-16-X-S4-MU: KAIROSNAME: C922
C1091 = 10P-50-N-S2-MU: KAIROSNAME: C320
R168 R170 R176 R178 R180 R182 R646 R647 R664 R666 = 42.2-1-S2
R172 R662 = 0-5-S2
R234 R1117-R1119 = 0-1-S4-YA
R659 R672 RB1 RB2 = 10K-1-S2-WA
R405-R416 R420 R422 R648-R650 R658 R661 R663 R709-R714 = 4.7K-1-S2
R1088 R1103 R1114 = 42.2-1-S2: KAIROSNAME: R178
R1089 R1106 R1115 = 42.2-1-S2: KAIROSNAME: R176
R1098 = 4.7K-1-S2: KAIROSNAME: R663
R1099 = 42.2-1-S2: KAIROSNAME: R168
R1100 = 42.2-1-S2: KAIROSNAME: R170
R1101 = 4.7K-1-S2: KAIROSNAME: R661
R1102 = 0-5-S2: KAIROSNAME: R662
R1104 = 0-5-S2: KAIROSNAME: R172
R1105 = 10K-1-S2-WA: KAIROSNAME: R659
R1107 = 42.2-1-S2: KAIROSNAME: R646
R1108 = 10K-1-S2-WA: KAIROSNAME: R672
R1109 = 42.2-1-S2: KAIROSNAME: R647
R1110 = 42.2-1-S2: KAIROSNAME: R180
R1111 = 42.2-1-S2: KAIROSNAME: R182
U408 U409 = CBTL06GP213EE-TFBGA50
U455 = CBTL06GP213EE-TFBGA50: KAIROSNAME: U408
U456 = CBTL06GP213EE-TFBGA50: KAIROSNAME: U409
C400 C407 C412 C416 C895 C956 C984 C986 = 2.2U-10-X-S4-MU
C402 = 4.7U-6.3-X-S4-MU
C403 = 22U-16-X5R-SA-SS
C404 = 10U-25-X-S6-MU
C405 = 1U-10-X-S4-MU
C1082 = 0.1U-16-X-S4-MU: KAIROSNAME: C955
C1083 = 0.1U-16-X-S4-MU: KAIROSNAME: C957
C1085 = 2.2U-10-X-S4-MU: KAIROSNAME: C956
R400 R403 R404 R589-R603 R751-R759 R766 RB501 RB502 SR1-SR48 = 0-5-S4
R401 = 523-1-S4
R402 = 1.2K-1-S4
R925 R929 R933 R937 R941 R945 = 4.7K-1-S2: KAIROSNAME: R747
R926 R932 R936 R940 R944 R948 R952 = 4.7K-1-S2: KAIROSNAME: R744
R927 R930 R934 R938 R942 R946 R950 = 4.7K-1-S2: KAIROSNAME: R725
R928 R931 R935 R939 R943 R947 = 4.7K-1-S2: KAIROSNAME: R731
R1093 = 4.7K-1-S2: KAIROSNAME: R712
R1097 = 4.7K-1-S2: KAIROSNAME: R713
U70 U403 U434 U435 = 74HC244BQ-DHVQFN20
U71 = R1173H001B-1A-A-SOT-89-5
U72 U74 U75 U77 U80 U405 U413 U415 = ULN2003AIPW-TSSOP16
U73 U76 U79 U414 = 74HC04BQ-DHVQFN14: IC~INVERTER~74HC04PW~Hex_inverter~TSSOP~PHILIPS; Package: TSSOP; PartGroup: INVERTER; PartNumber: 219100047351; PinCount: 14; ValueCell: 74HC04PW~~14TSSOP-0_65; Datasheet: K:\01_Library\02_Datasheet\Application IC_Datasheet\74HC04PW.pdf
U453 = ULN2003AIPW-TSSOP16: KAIROSNAME: U413
U454 = 74HC04BQ-DHVQFN14: IC~INVERTER~74HC04PW~Hex_inverter~TSSOP~PHILIPS; KAIROSNAME: U414; Package: TSSOP; PartGroup: INVERTER; PartNumber: 219100047351; PinCount: 14; ValueCell: 74HC04PW~~14TSSOP-0_65; Datasheet: K:\01_Library\02_Datasheet\Application IC_Datasheet\74HC04PW.pdf
Ubit_3V3_UP UT_UP5V = TP03-D
K109 K110 = G6K-2P-Y5VDC-A: KAIROSNAME: K107
LDB1 = LDG-2-S8
LRB1 = 330-1-S6
RB507-RB516 = 0-5-S4: KAIROSNAME: RB501
SC1-SC48 = 0.01U-50-X7R-S4-MU
SK1-SK8 = G6K-2P-Y5VDC-A
UB1 = AT24C04C-SSHM-SO8

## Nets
DGND: C302.2 C309.2 C310.2 C318.2 C320.2 C400.2 C401.2 C402.2 C403.2 C404.2 C405.2 C406.2 C407.2 C408.2 C409.2 C410.2 C411.2 C412.2 C413.2 C415.2 C416.2 C417.2 C894.2 C895.2 C910.2 C922.1 C923.1 C924.2 C955.2 C956.2 C957.2 C958.2 C983.2 C984.2 C985.2 C986.2 C1082.2 C1083.2 C1085.2 C1086.2 C1087.2 C1088.2 C1089.1 C1090.1 C1091.2 C1093.2 CA1.2 CA2.2 CA7.2 CA8.2 CA19.2 CA20.2 CA21.2 CA22.2 CA23.2 CA24.2 CA25.2 CA26.2 CA27.2 CA34.2 CA35.2 CA36.2 CA37.2 CA38.2 CA39.2 CC1.2 CC2.2 CC3.2 CC4.2 CC5.2 CC6.2 CC7.2 CC8.2 CC9.2 CC12.2 CC13.2 CC14.2 CC15.2 CC16.2 CC70.2 CC71.2 CC73.2 CC84.2 CC85.2 CC86.2 CC87.2 CC88.2 CC89.2 CC90.2 CC91.2 CC92.2 CC96.2 CC101.2 CC103.2 CC105.2 CC112.2 CC130.2 CC182.2 CC195.2 CC202.2 CC211.2 CC212.2 CC213.2 CC214.2 CC215.2 CC216.2 CC217.2 CC218.2 CC219.2 CC220.2 CON1.9(GND-1) CON1.10(GND-2) CON1.11(GND-3) CON1.12(GND-4) CON1.19(GND-5) CON1.20(GND-6) CON1.21(GND-7) CON1.22(GND-8) R401.2 R659.2 R672.2 R1105.2 R1108.2 RB501.2 RB502.2 RB507.2 RB508.2 RB509.2 RB510.2 RB511.2 RB512.2 RB513.2 RB514.2 RB515.2 RB516.2 SA2.1 SA7.1 SA10.1 SA15.1 SA18.1 SA20.1 SA22.1 SA24.1 SA26.1 SC1.2 SC2.2 SC3.2 SC4.2 SC5.2 SC6.2 SC7.2 SC8.2 SC9.2 SC10.2 SC11.2 SC12.2 SC13.2 SC14.2 SC15.2 SC16.2 SC17.2 SC18.2 SC19.2 SC20.2 SC21.2 SC22.2 SC23.2 SC24.2 SC25.2 SC26.2 SC27.2 SC28.2 SC29.2 SC30.2 SC31.2 SC32.2 SC33.2 SC34.2 SC35.2 SC36.2 SC37.2 SC38.2 SC39.2 SC40.2 SC41.2 SC42.2 SC43.2 SC44.2 SC45.2 SC46.2 SC47.2 SC48.2 U70.1(1OE#) U70.10(GND) U70.19(2OE#) U70.EP(EP(GND)) U70.G1 U70.G2 U70.G3 U71.2(GND) U72.8(E) U73.7(GND) U73.EP(EP(GND)) U74.8(E) U75.8(E) U76.7(GND) U76.EP(EP(GND)) U77.8(E) U79.7(GND) U79.EP(EP(GND)) U80.8(E) U403.1(1OE#) U403.10(GND) U403.19(2OE#) U403.EP(EP(GND)) U403.G1 U403.G2 U403.G3 U405.8(E) U408.B3(GND) U408.C8(GND) U408.G2(GND) U408.G8(GND) U408.H4(GND) U408.H7(GND) U409.B3(GND) U409.C8(GND) U409.G2(GND) U409.G8(GND) U409.H4(GND) U409.H7(GND) U413.8(E) U414.7(GND) U414.EP(EP(GND)) U415.8(E) U434.1(1OE#) U434.10(GND) U434.19(2OE#) U434.EP(EP(GND)) U434.G1 U434.G2 U434.G3 U435.1(1OE#) U435.10(GND) U435.19(2OE#) U435.EP(EP(GND)) U435.G1 U435.G2 U435.G3 U453.8(E) U454.7(GND) U454.EP(EP(GND)) U455.B3(GND) U455.C8(GND) U455.G2(GND) U455.G8(GND) U455.H4(GND) U455.H7(GND) U456.B3(GND) U456.C8(GND) U456.G2(GND) U456.G8(GND) U456.H4(GND) U456.H7(GND) ; also on sheet 1 2 3 4 5 6 7 8 9 10 11 12 13 14 21 22 23 24 25 26 27 28 30 31 32 33 34 35 36 37
5SA_RCBIT_01: U72.14(3C)
5SA_RCBIT_02: U413.15(2C)
5SA_RCBIT_03: U453.16(1C)
5SA_RCBIT_04: U405.14(3C)
5SA_RCBIT_05: U453.15(2C)
5SA_RCBIT_06: U405.15(2C)
5SA_RCBIT_07: U72.16(1C)
5SA_RCBIT_08: U413.16(1C)
5SA_RCBIT_09: U413.14(3C)
5SA_RCBIT_10: U415.16(1C)
5SA_RCBIT_11: U415.14(3C)
5SA_RCBIT_12: U415.15(2C)
5SA_RCBIT_13: U405.16(1C)
5SA_SCBIT_01: U434.18(1Y0)
5SA_SCBIT_02: U403.12(1Y3)
5SA_SCBIT_03: U434.16(1Y1)
5SA_SCBIT_04: U403.14(1Y2)
5SA_SCBIT_05: U70.16(1Y1)
5SA_SCBIT_06: U70.12(1Y3)
5SA_SCBIT_07: U403.18(1Y0)
5SA_SCBIT_08: U434.12(1Y3)
5SA_SCBIT_09: U435.16(1Y1)
5SA_SCBIT_10: U435.18(1Y0)
5SA_SCBIT_11: U434.14(1Y2)
5SA_SCBIT_12: U403.16(1Y1)
5SA_SCBIT_13: U70.14(1Y2)
BF_RLY01: R405.2 U73.1(1A)
BF_RLY02: R406.2 U73.3(2A)
BF_RLY03: R407.2 U73.5(3A)
BF_RLY04: R408.2 U73.9(4A)
BF_RLY05: R409.2 U73.11(5A)
BF_RLY06: R410.2 U73.13(6A)
BF_RLY07: R411.2 U76.1(1A)
BF_RLY08: R415.2 U76.3(2A)
BF_RLY09: R416.2 U76.5(3A)
BF_RLY10: R412.2 U76.9(4A)
BF_RLY11: R413.2 U76.11(5A)
BF_RLY12: R414.2 U76.13(6A)
BF_RLY13: R422.2 U79.1(1A)
BF_RLY14: R420.2 U79.3(2A)
BF_RLY15: R648.2 U79.5(3A)
BF_RLY16: R649.2 U79.9(4A)
BF_RLY17: R650.2 U79.11(5A)
BF_RLY18: R658.2 U79.13(6A)
BF_RLY19: R712.2 U414.1(1A)
BF_RLY20: R713.2 U414.3(2A)
BF_RLY21: R711.2 U414.5(3A)
BF_RLY22: R709.2 U414.9(4A)
BF_RLY23: R710.2 U414.11(5A)
BF_RLY24: R714.2 U414.13(6A)
BF_RLY25: R1093.2 U454.1(1A)
BF_RLY26: R1097.2 U454.3(2A)
BF_SW01: R400.2 R926.2
BF_SW02: R589.2 R927.2
BF_SW03: R590.2 R925.2
BF_SW04: R591.2 R928.2
BF_SW05: R592.2 R932.2
BF_SW06: R593.2 R930.2
BF_SW07: R594.2 R929.2
BF_SW08: R595.2 R931.2
BF_SW09: R603.2 R936.2
BF_SW10: R596.2 R934.2
BF_SW11: R597.2 R933.2
BF_SW12: R598.2 R935.2
BF_SW13: R599.2 R940.2
BF_SW14: R600.2 R938.2
BF_SW15: R601.2 R937.2
BF_SW16: R602.2 R939.2
BF_SW17: R751.2 R944.2
BF_SW18: R758.2 R942.2
BF_SW19: R753.2 R941.2
BF_SW20: R755.2 R943.2
BF_SW21: R757.2 R948.2
BF_SW22: R752.2 R946.2
BF_SW23: R754.2 R945.2
BF_SW24: R756.2 R947.2
BF_SW25: R759.2 R952.2
BF_SW26: R766.2 R950.2
S1_3V3_RX0_MIPI: BDB5.2 C922.2 R661.2 U408.A2(VDD) U408.J4(VDD)
S1_3V3_RX1_MIPI: BDB6.2 C923.2 R663.2 U409.A2(VDD) U409.J4(VDD)
S1_3V3_TX0_MIPI: BDB8.2 C1090.2 R1101.2 U455.A2(VDD) U455.J4(VDD)
S1_3V3_TX1_MIPI: BDB7.2 C1089.2 R1098.2 U456.A2(VDD) U456.J4(VDD)
S1_AWG_3SHARE+: K109.2 ; also on sheet 31
S1_B_DCH001: CC195.1 SITE1.M18(VDDP18_LDO_P0)
S1_CON1_0V6: CON1.5(LPDDR4X_0V6-1) CON1.6(LPDDR4X_0V6-2)
S1_CON1_0V8: CON1.15(VCORE_CPU-1) S1_DPS_SW1.13 S1_DPS_SW1.14 S1_DPS_SW1.15 S1_DPS_SW1.16 S1_DPS_SW6.13 S1_DPS_SW6.14 S1_DPS_SW6.15 S1_DPS_SW6.16
S1_CON1_1V1_1V2: CON1.25(DDR4_VDDIO-1) CON1.26(DDR4_VDDIO-2) S1_DPS_SW4.11 S1_DPS_SW4.12 S1_DPS_SW4.15 S1_DPS_SW4.16
S1_CON1_1V5_1V2: CON1.29(1V5_1V2-1) CON1.30(1V5_1V2-2) S1_DPS_SW4.9 S1_DPS_SW4.10 S1_DPS_SW4.13 S1_DPS_SW4.14
S1_CON1_1V8: CON1.7(1V8-1) CON1.8(1V8-2) S1_DPS_SW3.9 S1_DPS_SW3.10 S1_DPS_SW3.11 S1_DPS_SW3.12 S1_DPS_SW3.13 S1_DPS_SW3.14 S1_DPS_SW3.15 S1_DPS_SW3.16 S1_DPS_SW5.9 S1_DPS_SW5.10 S1_DPS_SW5.11 S1_DPS_SW5.12
S1_CON1_A3V3: CON1.3(A3V3) S1_DPS_SW2.9 S1_DPS_SW2.10 S1_DPS_SW2.11 S1_DPS_SW2.12 S1_DPS_SW2.13 S1_DPS_SW2.14 S1_DPS_SW2.15 S1_DPS_SW2.16
S1_CON1_B3V3: CON1.4(B3V3) S1_DPS_SW5.13 S1_DPS_SW5.14 S1_DPS_SW5.15 S1_DPS_SW5.16
S1_CON1_CORE_0V9: CON1.13(VCORE_CORE-1) CON1.14(VCORE_CORE-2) S1_DPS_SW1.9 S1_DPS_SW1.10 S1_DPS_SW1.11 S1_DPS_SW1.12 S1_DPS_SW6.9 S1_DPS_SW6.10 S1_DPS_SW6.11 S1_DPS_SW6.12
S1_CON1_CPU_0V9: CON1.16(VCORE_CPU-2)
S1_CON1_DDR2DDR3: CON1.23(DDR2DDR3-1) CON1.24(DDR2DDR3-2)
S1_CON1_IPU_0V9: CON1.17(VCORE_IPU-1) CON1.18(VCORE_IPU-2)
S1_CON1_VDD_DSP: CON1.27(VDD_DSP-1) CON1.28(VDD_DSP-2)
S1_DPS3: CA20.1 CA21.1 CC84.1 CC85.1 CC86.1 CC87.1 CC88.1 CC89.1 CC90.1 CC91.1 CC92.1 S1_DPS_SW3.1 S1_DPS_SW3.2 S1_DPS_SW3.3 S1_DPS_SW3.4 SA17.1 SITE1.F4(VDDP18_P1) SITE1.F17(AVDD18_NODIE) SITE1.G5(AVDD18_MIPI_TX) SITE1.H4(AVDD18_USB) SITE1.J18(AVDD18_OTP) SITE1.L5(AVDD18_AUD) SITE1.R11(AVDD18_PLL_DDR) SITE1.R14(VDD1_DRAM[0]) SITE1.R15(VDD1_DRAM[1]) TP_DPS3.1(TP) ; also on sheet 31
S1_DPS4: CA34.1 CA35.1 CC182.1 CC202.1 S1_DPS_SW2.1 S1_DPS_SW2.2 S1_DPS_SW2.3 S1_DPS_SW2.4 SA19.1 SITE1.H19(AVDD33_ETH) SITE1.J5(AVDD33_USB) TP_DPS4.1(TP) ; also on sheet 31
S1_Mpdch37+: U408.B8(DIN2_0+)
S1_Mpdch37-: U408.B9(DIN2_0-)
S1_Mpdch38+: U455.B8(DIN2_0+)
S1_Mpdch38-: U455.B9(DIN2_0-)
S1_Mpdch39+: U408.D8(DIN2_1+)
S1_Mpdch39-: U408.D9(DIN2_1-)
S1_Mpdch40+: U455.D8(DIN2_1+)
S1_Mpdch40-: U455.D9(DIN2_1-)
S1_Mpdch41+: U408.E8(DIN2_2+)
S1_Mpdch41-: U408.E9(DIN2_2-)
S1_Mpdch42+: U455.E8(DIN2_2+)
S1_Mpdch42-: U455.E9(DIN2_2-)
S1_Mpdch43+: U409.B8(DIN2_0+)
S1_Mpdch43-: U409.B9(DIN2_0-)
S1_Mpdch44+: U456.B8(DIN2_0+)
S1_Mpdch44-: U456.B9(DIN2_0-)
S1_Mpdch45+: U409.D8(DIN2_1+)
S1_Mpdch45-: U409.D9(DIN2_1-)
S1_Mpdch46+: U456.D8(DIN2_1+)
S1_Mpdch46-: U456.D9(DIN2_1-)
S1_Mpdch47+: U409.E8(DIN2_2+)
S1_Mpdch47-: U409.E9(DIN2_2-)
S1_MUX_3V3: R234.2 R1117.2 R1118.2 R1119.2 ; also on sheet 31
S1_OUT_RX0_CH0_ABC_CASE+: SITE1.B10(PAD_OUTP_RX0_CH[0]) U408.B2(DOUT_0+)
S1_OUT_RX0_CH0_ABC_CASE-: SITE1.A10(PAD_OUTN_RX0_CH[0]) U408.B1(DOUT_0-)
S1_OUT_RX0_CH0_B_CASE+: R647.1 U408.B4(DIN1_0+)
S1_OUT_RX0_CH0_B_CASE-: R646.1 U408.A4(DIN1_0-)
S1_OUT_RX0_CH0_C_CASE: C309.1 R646.2 R647.2
S1_OUT_RX0_CH1_ABC_CASE+: SITE1.B9(PAD_OUTP_RX0_CH[1]) U408.D2(DOUT_1+)
S1_OUT_RX0_CH1_ABC_CASE-: SITE1.B8(PAD_OUTN_RX0_CH[1]) U408.D1(DOUT_1-)
S1_OUT_RX0_CH1_B_CASE+: R168.1 U408.B5(DIN1_1+)
S1_OUT_RX0_CH1_B_CASE-: R170.1 U408.A5(DIN1_1-)
S1_OUT_RX0_CH1_C_CASE: C310.1 R168.2 R170.2
S1_OUT_RX0_CH2_ABC_CASE+: SITE1.A8(PAD_OUTP_RX0_CH[2]) U408.E2(DOUT_2+)
S1_OUT_RX0_CH2_ABC_CASE-: SITE1.B7(PAD_OUTN_RX0_CH[2]) U408.E1(DOUT_2-)
S1_OUT_RX0_CH2_B_CASE+: R176.1 U408.B6(DIN1_2+)
S1_OUT_RX0_CH2_B_CASE-: R178.1 U408.A6(DIN1_2-)
S1_OUT_RX0_CH2_C_CASE: C318.1 R176.2 R178.2
S1_OUT_RX0_CH3_ABC_CASE+: SITE1.B6(PAD_OUTP_RX0_CH[3]) U409.B2(DOUT_0+)
S1_OUT_RX0_CH3_ABC_CASE-: SITE1.A6(PAD_OUTN_RX0_CH[3]) U409.B1(DOUT_0-)
S1_OUT_RX0_CH3_B_CASE+: R1089.1 U409.B4(DIN1_0+)
S1_OUT_RX0_CH3_B_CASE-: R1088.1 U409.A4(DIN1_0-)
S1_OUT_RX0_CH3_C_CASE: C302.1 R1088.2 R1089.2
S1_OUT_RX0_CH4_ABC_CASE+: SITE1.B5(PAD_OUTP_RX0_CH[4]) U409.D2(DOUT_1+)
S1_OUT_RX0_CH4_ABC_CASE-: SITE1.B4(PAD_OUTN_RX0_CH[4]) U409.D1(DOUT_1-)
S1_OUT_RX0_CH4_B_CASE+: R180.1 U409.B5(DIN1_1+)
S1_OUT_RX0_CH4_B_CASE-: R182.1 U409.A5(DIN1_1-)
S1_OUT_RX0_CH4_C_CASE: C320.1 R180.2 R182.2
S1_OUT_RX0_CH5_ABC_CASE+: SITE1.A4(PAD_OUTP_RX0_CH[5]) U409.E2(DOUT_2+)
S1_OUT_RX0_CH5_ABC_CASE-: SITE1.B3(PAD_OUTN_RX0_CH[5]) U409.E1(DOUT_2-)
S1_OUT_RX0_CH5_B_CASE+: R666.1 U409.B6(DIN1_2+)
S1_OUT_RX0_CH5_B_CASE-: R664.1 U409.A6(DIN1_2-)
S1_OUT_RX0_CH5_C_CASE: C924.1 R664.2 R666.2
S1_OUT_TX0_CH0_ABC_CASE+: SITE1.A2(PAD_OUTP_TX0_CH[0]) U455.B2(DOUT_0+)
S1_OUT_TX0_CH0_ABC_CASE-: SITE1.B1(PAD_OUTN_TX0_CH[0]) U455.B1(DOUT_0-)
S1_OUT_TX0_CH0_B_CASE+: R1109.1 U455.B4(DIN1_0+)
S1_OUT_TX0_CH0_B_CASE-: R1107.1 U455.A4(DIN1_0-)
S1_OUT_TX0_CH0_C_CASE: C1086.1 R1107.2 R1109.2
S1_OUT_TX0_CH1_ABC_CASE+: SITE1.C1(PAD_OUTP_TX0_CH[1]) U455.D2(DOUT_1+)
S1_OUT_TX0_CH1_ABC_CASE-: SITE1.C2(PAD_OUTN_TX0_CH[1]) U455.D1(DOUT_1-)
S1_OUT_TX0_CH1_B_CASE+: R1099.1 U455.B5(DIN1_1+)
S1_OUT_TX0_CH1_B_CASE-: R1100.1 U455.A5(DIN1_1-)
S1_OUT_TX0_CH1_C_CASE: C1087.1 R1099.2 R1100.2
S1_OUT_TX0_CH2_ABC_CASE+: SITE1.D2(PAD_OUTP_TX0_CH[2]) U455.E2(DOUT_2+)
S1_OUT_TX0_CH2_ABC_CASE-: SITE1.E1(PAD_OUTN_TX0_CH[2]) U455.E1(DOUT_2-)
S1_OUT_TX0_CH2_B_CASE+: R1106.1 U455.B6(DIN1_2+)
S1_OUT_TX0_CH2_B_CASE-: R1103.1 U455.A6(DIN1_2-)
S1_OUT_TX0_CH2_C_CASE: C1088.1 R1103.2 R1106.2
S1_OUT_TX0_CH3_ABC_CASE+: SITE1.E2(PAD_OUTP_TX0_CH[3]) U456.B2(DOUT_0+)
S1_OUT_TX0_CH3_ABC_CASE-: SITE1.F2(PAD_OUTN_TX0_CH[3]) U456.B1(DOUT_0-)
S1_OUT_TX0_CH3_B_CASE+: R1115.1 U456.B4(DIN1_0+)
S1_OUT_TX0_CH3_B_CASE-: R1114.1 U456.A4(DIN1_0-)
S1_OUT_TX0_CH3_C_CASE: C1093.1 R1114.2 R1115.2
S1_OUT_TX0_CH4_ABC_CASE+: SITE1.G1(PAD_OUTP_TX0_CH[4]) U456.D2(DOUT_1+)
S1_OUT_TX0_CH4_ABC_CASE-: SITE1.G2(PAD_OUTN_TX0_CH[4]) U456.D1(DOUT_1-)
S1_OUT_TX0_CH4_B_CASE+: R1110.1 U456.B5(DIN1_1+)
S1_OUT_TX0_CH4_B_CASE-: R1111.1 U456.A5(DIN1_1-)
S1_OUT_TX0_CH4_C_CASE: C1091.1 R1110.2 R1111.2
S1_PWR_F001: CA26.1 CA27.1 CC112.1 S1_DPS_SW6.1 S1_DPS_SW6.2 S1_DPS_SW6.3 S1_DPS_SW6.4 S1_DPS_SW6.5 S1_DPS_SW6.6 S1_DPS_SW6.7 S1_DPS_SW6.8 SA16.1 SITE1.F15(DVDD_NODIE) TP_DPS2.1(TP)
S1_PWR_F004: CA22.1 CA23.1 CC96.1 S1_DPS_SW2.5 S1_DPS_SW2.6 S1_DPS_SW2.7 S1_DPS_SW2.8 SA21.1 SITE1.E10(AVDD33_RTC) TP_DPS5.1(TP)
S1_PWR_F005: CA7.1 CA8.1 CC70.1 CC71.1 CC73.1 S1_DPS_SW5.1 S1_DPS_SW5.2 S1_DPS_SW5.3 S1_DPS_SW5.4 S1_DPS_SW5.5 S1_DPS_SW5.6 S1_DPS_SW5.7 S1_DPS_SW5.8 SA8.1 SITE1.G18(VDDP3318_PM) SITE1.N17(VDDP3318_P0) SITE1.P3(VDDP3318_P2) TP_DPS6.1(TP)
S1_PWR_F006: CA24.1 CA25.1 CC101.1 CC103.1 CC105.1 S1_DPS_SW4.1 S1_DPS_SW4.2 S1_DPS_SW4.3 S1_DPS_SW4.4 SA9.1 SITE1.T13(VDD2_DRAM[0]) SITE1.T14(VDD2_DRAM[1]) SITE1.U13(VDD2_DRAM[2]) TP_DPS7.1(TP)
S1_PWR_F007: CA36.1 CA37.1 CC211.1 CC212.1 CC213.1 S1_DPS_SW4.5 S1_DPS_SW4.6 S1_DPS_SW4.7 S1_DPS_SW4.8 SA23.1 SITE1.T10(VDDQ_DRAM[0]) SITE1.T11(VDDQ_DRAM[1]) SITE1.U11(VDDQ_DRAM[2]) TP_DPS8.1(TP)
S1_PWR_F008: CA38.1 CA39.1 CC220.1 S1_DPS_SW3.5 S1_DPS_SW3.6 S1_DPS_SW3.7 S1_DPS_SW3.8 SA25.1 SITE1.K19(AVDD18_XTAL) TP_DPS9.1(TP)
S1_PWR_GS001: SA15.2
S1_PWR_GS002: SA18.2
S1_PWR_GS003: SA20.2
S1_PWR_GS004: SA22.2
S1_PWR_GS005: SA7.2
S1_PWR_GS006: SA10.2
S1_PWR_GS007: SA24.2
S1_PWR_GS008: SA26.2
S1_PWR_M_F001: CA1.1 CA2.1 CC1.1 CC2.1 CC3.1 CC4.1 CC5.1 CC6.1 CC7.1 CC8.1 CC9.1 CC12.1 CC13.1 CC14.1 CC15.1 CC16.1 CC130.1 CC214.1 CC215.1 CC216.1 CC217.1 CC218.1 CC219.1 K96.4 K96.9 S1_DPS_SW1.1 S1_DPS_SW1.2 S1_DPS_SW1.3 S1_DPS_SW1.4 S1_DPS_SW1.5 S1_DPS_SW1.6 S1_DPS_SW1.7 S1_DPS_SW1.8 SA1.1 SITE1.F6(AVDDL_MIPI_RX) SITE1.F7(VDD_CPU[0]) SITE1.F8(VDD_CPU[1]) SITE1.G6(AVDDL_MIPI_TX) SITE1.G7(VDD_CPU[2]) SITE1.G8(VDD_CPU[3]) SITE1.G10(VDD[0]) SITE1.G11(VDD[1]) SITE1.H7(VDD_CPU[4]) SITE1.H8(VDD_CPU[5]) SITE1.H10(VDD[2]) SITE1.H11(VDD[3]) SITE1.H12(VDD[4]) SITE1.J10(VDD[5]) SITE1.J11(VDD[6]) SITE1.J12(VDD[7]) SITE1.J13(VDD[8]) SITE1.K10(VDD[9]) SITE1.K11(VDD[10]) SITE1.K12(VDD[11]) SITE1.K13(VDD[12]) TP_DPS1.1(TP)
S1_PWR_M_GS001: SA2.2
S1_PWR_M_S001: SA1.2
S1_PWR_S001: SA16.2
S1_PWR_S002: SA17.2
S1_PWR_S003: SA19.2
S1_PWR_S004: SA21.2
S1_PWR_S005: SA8.2
S1_PWR_S006: SA9.2
S1_PWR_S007: SA23.2
S1_PWR_S008: SA25.2
S2_AWG_3SHARE+: K109.7 ; also on sheet 32
S3_AWG_3SHARE+: K110.2 ; also on sheet 30
S4_AWG_3SHARE+: K110.7 ; also on sheet 34
S5_AWG_3SHARE+: K109.4 ; also on sheet 33
S6_AWG_3SHARE+: K109.5 ; also on sheet 36
S7_AWG_3SHARE+: K110.4 ; also on sheet 35
S8_AWG_3SHARE+: K110.5 ; also on sheet 37
SA_CBIT_R96: K96.12(V-)
SA_CBIT_S20: R662.2 R1102.2
SA_CBIT_S29: R172.2 R1104.2
SA_RCBIT_01: U74.16(1C)
SA_RCBIT_02: U80.14(3C)
SA_RCBIT_03: U75.14(3C)
SA_RCBIT_04: U72.15(2C)
SA_RCBIT_05: U75.15(2C)
SA_RCBIT_06: U80.16(1C)
SA_RCBIT_07: U74.15(2C)
SA_RCBIT_08: U80.15(2C)
SA_RCBIT_09: U75.16(1C)
SA_RCBIT_10: U77.16(1C)
SA_RCBIT_11: U77.15(2C)
SA_RCBIT_12: U77.14(3C)
SA_RCBIT_13: U74.14(3C)
SA_SCBIT_01: U70.3(2Y0)
SA_SCBIT_02: U70.5(2Y1)
SA_SCBIT_03: U70.18(1Y0)
SA_SCBIT_04: U70.7(2Y2)
SA_SCBIT_05: U403.9(2Y3)
SA_SCBIT_06: U403.5(2Y1)
SA_SCBIT_07: U403.3(2Y0)
SA_SCBIT_08: U434.5(2Y1)
SA_SCBIT_09: U434.9(2Y3)
SA_SCBIT_10: U434.7(2Y2)
SA_SCBIT_11: U434.3(2Y0)
SA_SCBIT_12: U70.9(2Y3)
SA_SCBIT_13: U403.7(2Y2)
SK_RLY01: SK1.8(V-)
SK_RLY02: SK2.8(V-)
SK_RLY03: SK3.8(V-)
SK_RLY04: SK4.8(V-)
SK_RLY05: SK5.8(V-)
SK_RLY06: SK6.8(V-)
SK_RLY07: SK7.8(V-)
SK_RLY08: SK8.8(V-)
SK_RLY109: K109.8(V-)
SK_RLY110: K110.8(V-)
SX_MCB_01+: K109.3
SX_MCB_02+: K109.6
SX_MCB_03+: K110.3
SX_MCB_04+: K110.6
Ubit_3V3_UP: BD5.1 BD1721.1 BD1722.1 BD1723.1 R403.1
UDBGND: LDB1.2(B) RB501.1 RB502.1 RB507.1 RB508.1 RB509.1 RB510.1 RB511.1 RB512.1 RB513.1 RB514.1 RB515.1 RB516.1 UB1.1(NC) UB1.2(A1/NC) UB1.3(A2) UB1.4(GND) UB1.7(WP) XC2.1 ; also on sheet 21 22 23 24 25 26 27 28
UT1_UP5V: C403.1 C404.1 C405.1 C406.1 C407.1 C408.1 C409.1 C410.1 C411.1 C412.1 C413.1 C415.1 C416.1 C417.1 C910.1 C955.1 C956.1 C957.1 C958.1 C1082.1 C1083.1 C1085.1 J1.1 J2.1 K96.1(V+) K109.1(V+) K110.1(V+) LRB1.1 R404.2 R405.1 R406.1 R407.1 R408.1 R409.1 R410.1 R411.1 R412.1 R413.1 R414.1 R415.1 R416.1 R420.1 R422.1 R648.1 R649.1 R650.1 R658.1 R709.1 R710.1 R711.1 R712.1 R713.1 R714.1 R1093.1 R1097.1 RB1.1 RB2.1 SK1.1(V+) SK2.1(V+) SK3.1(V+) SK4.1(V+) SK5.1(V+) SK6.1(V+) SK7.1(V+) SK8.1(V+) U71.4(VDD) U72.9(COM) U73.14(VCC) U74.9(COM) U75.9(COM) U76.14(VCC) U77.9(COM) U79.14(VCC) U80.9(COM) U405.9(COM) U413.9(COM) U414.14(VCC) U415.9(COM) U453.9(COM) U454.14(VCC) UB1.8(VCC) UT_UP5V.1(TP) XC2.2 ; also on sheet 2 4 6 8 10 12 14 21 22 23 24 25 26 27 28 30 31 32 33 34 35 36 37
UT1_UW14: RB1.2 UB1.6(SCL) ; also on sheet 23
UT1_UW15: RB2.2 UB1.5(SDA) ; also on sheet 23
N17578091: SR3.2 STP3.1(TP)
N17578095: SR4.2 STP4.1(TP)
N17578103: SR5.2 STP5.1(TP)
N17578107: SC4.1 SK1.7 SR5.1
N17578109: SR6.2 STP6.1(TP)
N17578111: SC1.1 SK1.6 SR2.2
N17578117: SR2.1 STP2.1(TP)
N17578119: SC6.1 SK1.2 SR3.1
N17578121: SC2.1 SK1.3 SR1.2
N17578131: SC3.1 SK1.5 SR6.1
N17578138: SR9.2 STP9.1(TP)
N17578142: SR10.2 STP10.1(TP)
N17578153: SC10.1 SK2.7 SR11.1
N17578155: SR11.2 STP11.1(TP)
N17578165: SR12.2 STP12.1(TP)
N17578169: SC7.1 SK2.6 SR8.2
N17578175: SR8.1 STP8.1(TP)
N17578179: SC12.1 SK2.2 SR9.1
N17578181: SC9.1 SK2.5 SR12.1
N17578183: SC8.1 SK2.3 SR7.2
N17578209: SR7.1 STP7.1(TP)
N17578211: SC11.1 SK2.4 SR10.1
N17578235: SC5.1 SK1.4 SR4.1
N17578245: SR1.1 STP1.1(TP)
N17578251: SR18.2 STP16.1(TP)
N17578253: SR14.2 STP14.1(TP)
N17578257: SC17.1 SK3.7 SR14.1
N17578263: SR17.2 STP15.1(TP)
N17578267: SR13.1 STP18.1(TP)
N17578271: SC14.1 SK3.6 SR13.2
N17578275: SR15.2 STP13.1(TP)
N17578283: SC13.1 SK3.5 SR15.1
N17578291: SC15.1 SK3.3 SR16.2
N17578297: SC18.1 SK3.2 SR17.1
N17578299: SR16.1 STP17.1(TP)
N17578323: SC16.1 SK3.4 SR18.1
N17578329: SR23.2 STP21.1(TP)
N17578337: SR24.2 STP22.1(TP)
N17578341: SR20.2 STP20.1(TP)
N17578345: SC23.1 SK4.7 SR20.1
N17578351: SC19.1 SK4.5 SR21.1
N17578353: SC24.1 SK4.2 SR23.1
N17578355: SR19.1 STP24.1(TP)
N17578359: SC20.1 SK4.6 SR19.2
N17578363: SR21.2 STP19.1(TP)
N17578379: SC21.1 SK4.3 SR22.2
N17578383: SC22.1 SK4.4 SR24.1
N17578387: SR22.1 STP23.1(TP)
N17981963: U453.1(1B) U454.2(1Y)
N17981973: U453.2(2B) U454.4(2Y)
N18477102: U79.6(3Y) U80.3(3B)
N18477108: U79.4(2Y) U80.2(2B)
N18477229: U79.10(5Y) U405.2(2B)
N18477291: U79.8(4Y) U405.1(1B)
N18477301: U79.12(6Y) U405.3(3B)
N18479086: U414.10(5Y) U415.2(2B)
N18479100: U413.3(3B) U414.6(3Y)
N18479120: U413.1(1B) U414.2(1Y)
N18479142: U413.2(2B) U414.4(2Y)
N18479202: U414.8(4Y) U415.1(1B)
N18479218: U414.12(6Y) U415.3(3B)
N18480061: R601.1 U403.13(2A2)
N18480064: R602.1 U403.11(2A3)
N18480115: BD1721.2 C894.1 C895.1 R933.1 R934.1 R935.1 R936.1 R937.1 R938.1 R939.1 R940.1 U403.20(VCC)
N18480820: BD1722.2 C983.1 C984.1 R941.1 R942.1 R943.1 R944.1 R945.1 R946.1 R947.1 R948.1 U434.20(VCC)
N18480908: R758.1 U434.4(1A1)
N18480914: R753.1 U434.6(1A2)
N18480920: R755.1 U434.8(1A3)
N18480930: R757.1 U434.17(2A0)
N18480954: R751.1 U434.2(1A0)
N18480970: R752.1 U434.15(2A1)
N18480990: R754.1 U434.13(2A2)
N18480996: R756.1 U434.11(2A3)
N18482064: BD1723.2 C985.1 C986.1 R950.1 R952.1 U435.20(VCC)
N18482160: R766.1 U435.4(1A1)
N18482210: R759.1 U435.2(1A0)
N19145542: SR30.2 STP28.1(TP)
N19145546: SR26.2 STP26.1(TP)
N19145550: SC29.1 SK5.7 SR26.1
N19145556: SR29.2 STP27.1(TP)
N19145558: SC30.1 SK5.2 SR29.1
N19145560: SR25.1 STP30.1(TP)
N19145564: SC26.1 SK5.6 SR25.2
N19145568: SR27.2 STP25.1(TP)
N19145576: SC25.1 SK5.5 SR27.1
N19145584: SC27.1 SK5.3 SR28.2
N19145590: SC28.1 SK5.4 SR30.1
N19145592: SR28.1 STP29.1(TP)
N19145780: SR36.2 STP34.1(TP)
N19145784: SR35.2 STP33.1(TP)
N19145790: SR33.2 STP31.1(TP)
N19145800: SR32.2 STP32.1(TP)
N19145804: SC35.1 SK6.7 SR32.1
N19145813: SC33.1 SK6.3 SR34.2
N19145817: SC31.1 SK6.5 SR33.1
N19145819: SC36.1 SK6.2 SR35.1
N19145821: SR31.1 STP36.1(TP)
N19145825: SC32.1 SK6.6 SR31.2
N19145869: SC34.1 SK6.4 SR36.1
N19145875: SR34.1 STP35.1(TP)
N19146153: SR41.2 STP39.1(TP)
N19146155: SR39.2 STP37.1(TP)
N19146167: SR42.2 STP41.1(TP)
N19146177: SC37.1 SK7.5 SR39.1
N19146179: SC39.1 SK7.3 SR40.2
N19146183: SC41.1 SK7.7 SR38.1
N19146185: SR38.2 STP38.1(TP)
N19146193: SC42.1 SK7.2 SR41.1
N19146199: SC38.1 SK7.6 SR37.2
N19146205: SR37.1 STP42.1(TP)
N19146217: SC40.1 SK7.4 SR42.1
N19146247: SR40.1 STP40.1(TP)
N19146496: SR47.2 STP45.1(TP)
N19146500: SR48.2 STP47.1(TP)
N19146502: SR44.2 STP44.1(TP)
N19146512: SR45.2 STP43.1(TP)
N19146518: SC44.1 SK8.6 SR43.2
N19146522: SR43.1 STP48.1(TP)
N19146524: SC48.1 SK8.2 SR47.1
N19146526: SC43.1 SK8.5 SR45.1
N19146528: SC45.1 SK8.3 SR46.2
N19146532: SC47.1 SK8.7 SR44.1
N19146554: SR46.1 STP46.1(TP)
N19146556: SC46.1 SK8.4 SR48.1
N19656281: BD5.2 C400.1 C401.1 R925.1 R926.1 R927.1 R928.1 R929.1 R930.1 R931.1 R932.1 U70.20(VCC)
N20622637: CA19.1 K96.5 K96.8
N21251868: R172.1 U408.A1(GPU_SEL)
N21251873: R661.1 U408.B7(/XSD)
N21251881: R662.1 U409.A1(GPU_SEL)
N21251886: R663.1 U409.B7(/XSD)
N21251935: R672.1 U409.C2(DDC_AUX_SEL)
N21252012: R659.1 U408.C2(DDC_AUX_SEL)
N21253598: R1104.1 U455.A1(GPU_SEL)
N21253603: R1101.1 U455.B7(/XSD)
N21253611: R1102.1 U456.A1(GPU_SEL)
N21253616: R1098.1 U456.B7(/XSD)
N21253665: R1108.1 U456.C2(DDC_AUX_SEL)
N21253742: R1105.1 U455.C2(DDC_AUX_SEL)
N21924858: BDB5.1 R234.1
N21924889: BDB6.1 R1117.1
N21924929: BDB8.1 R1118.1
N21924997: BDB7.1 R1119.1
N22558607: R400.1 U70.2(1A0)
N22558620: R404.1 U71.3(CE)
N22558621: C402.1 R402.1 R403.2 U71.5(VOUT) Ubit_3V3_UP.1(TP)
N22558623: R401.1 R402.2 U71.1(ADJ)
N22614163: CON1.2(5V-2) J2.2
N22614200: CON1.1(5V-1) J1.2
N23535319: LDB1.1(A) LRB1.2
N23799274: U73.2(1Y) U74.1(1B)
N23799277: U73.4(2Y) U74.2(2B)
N23799280: U73.6(3Y) U74.3(3B)
N23799283: U72.1(1B) U73.8(4Y)
N23799286: U72.2(2B) U73.10(5Y)
N23799289: U72.3(3B) U73.12(6Y)
N23799348: U76.2(1Y) U77.1(1B)
N23799351: U76.4(2Y) U77.2(2B)
N23799354: U76.6(3Y) U77.3(3B)
N23799357: U75.1(1B) U76.8(4Y)
N23799360: U75.2(2B) U76.10(5Y)
N23799363: U75.3(3B) U76.12(6Y)
N30783219: U79.2(1Y) U80.1(1B)
N31842551: R589.1 U70.4(1A1)
N31842593: R590.1 U70.6(1A2)
N31842638: R591.1 U70.8(1A3)
N31842671: R592.1 U70.17(2A0)
N31842704: R593.1 U70.15(2A1)
N31842737: R594.1 U70.13(2A2)
N31842770: R595.1 U70.11(2A3)
N31842787: R596.1 U403.4(1A1)
N31842830: R597.1 U403.6(1A2)
N31842855: R598.1 U403.8(1A3)
N31842884: R599.1 U403.17(2A0)
N31842923: R603.1 U403.2(1A0)
N31842948: R600.1 U403.15(2A1)

Not connected (* = marked no-connect by the designer): K96 3* 10*; U72 4(4B)* 5(5B)* 6(6B)* 7(7B)* 10(7C)* 11(6C)* 12(5C)* 13(4C)*; U74 4(4B)* 5(5B)* 6(6B)* 7(7B)* 10(7C)* 11(6C)* 12(5C)* 13(4C)*; U75 4(4B)* 5(5B)* 6(6B)* 7(7B)* 10(7C)* 11(6C)* 12(5C)* 13(4C)*; U77 4(4B)* 5(5B)* 6(6B)* 7(7B)* 10(7C)* 11(6C)* 12(5C)* 13(4C)*; U80 4(4B)* 5(5B)* 6(6B)* 7(7B)* 10(7C)* 11(6C)* 12(5C)* 13(4C)*; U405 4(4B)* 5(5B)* 6(6B)* 7(7B)* 10(7C)* 11(6C)* 12(5C)* 13(4C)*; U408 A8(DIN1_3+)* A9(DIN1_3-)* F1(DOUT_3-)* F2(DOUT_3+)* F8(DIN2_3+)* F9(DIN2_3-)* H1(AUX-)* H2(AUX+)* H3(HPD_2)* H5(DDC_CLK2)* H6(DAUX2+)* H8(DDC_CLK1)* H9(DAUX1+)* J1(HPDIN)* J2(HPD_1)* J3(DDC_CLK)* J5(DDC_DAT2)* J6(DAUX2-)* J7(DDC_DAT)* J8(DDC_DAT1)* J9(DAUX1-)*; U409 A8(DIN1_3+)* A9(DIN1_3-)* F1(DOUT_3-)* F2(DOUT_3+)* F8(DIN2_3+)* F9(DIN2_3-)* H1(AUX-)* H2(AUX+)* H3(HPD_2)* H5(DDC_CLK2)* H6(DAUX2+)* H8(DDC_CLK1)* H9(DAUX1+)* J1(HPDIN)* J2(HPD_1)* J3(DDC_CLK)* J5(DDC_DAT2)* J6(DAUX2-)* J7(DDC_DAT)* J8(DDC_DAT1)* J9(DAUX1-)*; U413 4(4B)* 5(5B)* 6(6B)* 7(7B)* 10(7C)* 11(6C)* 12(5C)* 13(4C)*; U415 4(4B)* 5(5B)* 6(6B)* 7(7B)* 10(7C)* 11(6C)* 12(5C)* 13(4C)*; U435 3(2Y0)* 5(2Y1)* 6(1A2)* 7(2Y2)* 8(1A3)* 9(2Y3)* 11(2A3)* 12(1Y3)* 13(2A2)* 14(1Y2)* 15(2A1)* 17(2A0)*; U453 3(3B)* 4(4B)* 5(5B)* 6(6B)* 7(7B)* 10(7C)* 11(6C)* 12(5C)* 13(4C)* 14(3C)*; U454 5(3A)* 6(3Y)* 8(4Y)* 9(4A)* 10(5Y)* 11(5A)* 12(6Y)* 13(6A)*; U455 A8(DIN1_3+)* A9(DIN1_3-)* F1(DOUT_3-)* F2(DOUT_3+)* F8(DIN2_3+)* F9(DIN2_3-)* H1(AUX-)* H2(AUX+)* H3(HPD_2)* H5(DDC_CLK2)* H6(DAUX2+)* H8(DDC_CLK1)* H9(DAUX1+)* J1(HPDIN)* J2(HPD_1)* J3(DDC_CLK)* J5(DDC_DAT2)* J6(DAUX2-)* J7(DDC_DAT)* J8(DDC_DAT1)* J9(DAUX1-)*; U456 A6(DIN1_2-)* A8(DIN1_3+)* A9(DIN1_3-)* B6(DIN1_2+)* E1(DOUT_2-)* E2(DOUT_2+)* E8(DIN2_2+)* E9(DIN2_2-)* F1(DOUT_3-)* F2(DOUT_3+)* F8(DIN2_3+)* F9(DIN2_3-)* H1(AUX-)* H2(AUX+)* H3(HPD_2)* H5(DDC_CLK2)* H6(DAUX2+)* H8(DDC_CLK1)* H9(DAUX1+)* J1(HPDIN)* J2(HPD_1)* J3(DDC_CLK)* J5(DDC_DAT2)* J6(DAUX2-)* J7(DDC_DAT)* J8(DDC_DAT1)* J9(DAUX1-)*

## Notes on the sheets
sheet 17
- 1.53A/0.7V/0.8V
- 0.05A/0.7V/0.8V
- 0.7A/1.8V
- 0.01A/3.3V
- POWER MODULE CONN
- 200uA/3.3V
- Place on the TOP
- 0.75A/3.3V/1.8V
- 0.1A/1.1V
- 0.03A/0.8V
- 0.02A/1.8V
- Trace Width: 20 mil
sheet 18
- 100 ohm DIFF
- 2023.10.30
- 100 ohm DIFF
- 2023.10.30
sheet 19
- 3.3V
sheet 20
- All UT_5V Merge
- MCB_CT1
- Apply GND shielding
- Spare Relay
